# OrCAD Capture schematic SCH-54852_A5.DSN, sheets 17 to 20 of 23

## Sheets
17 C-09 PMIC: size C
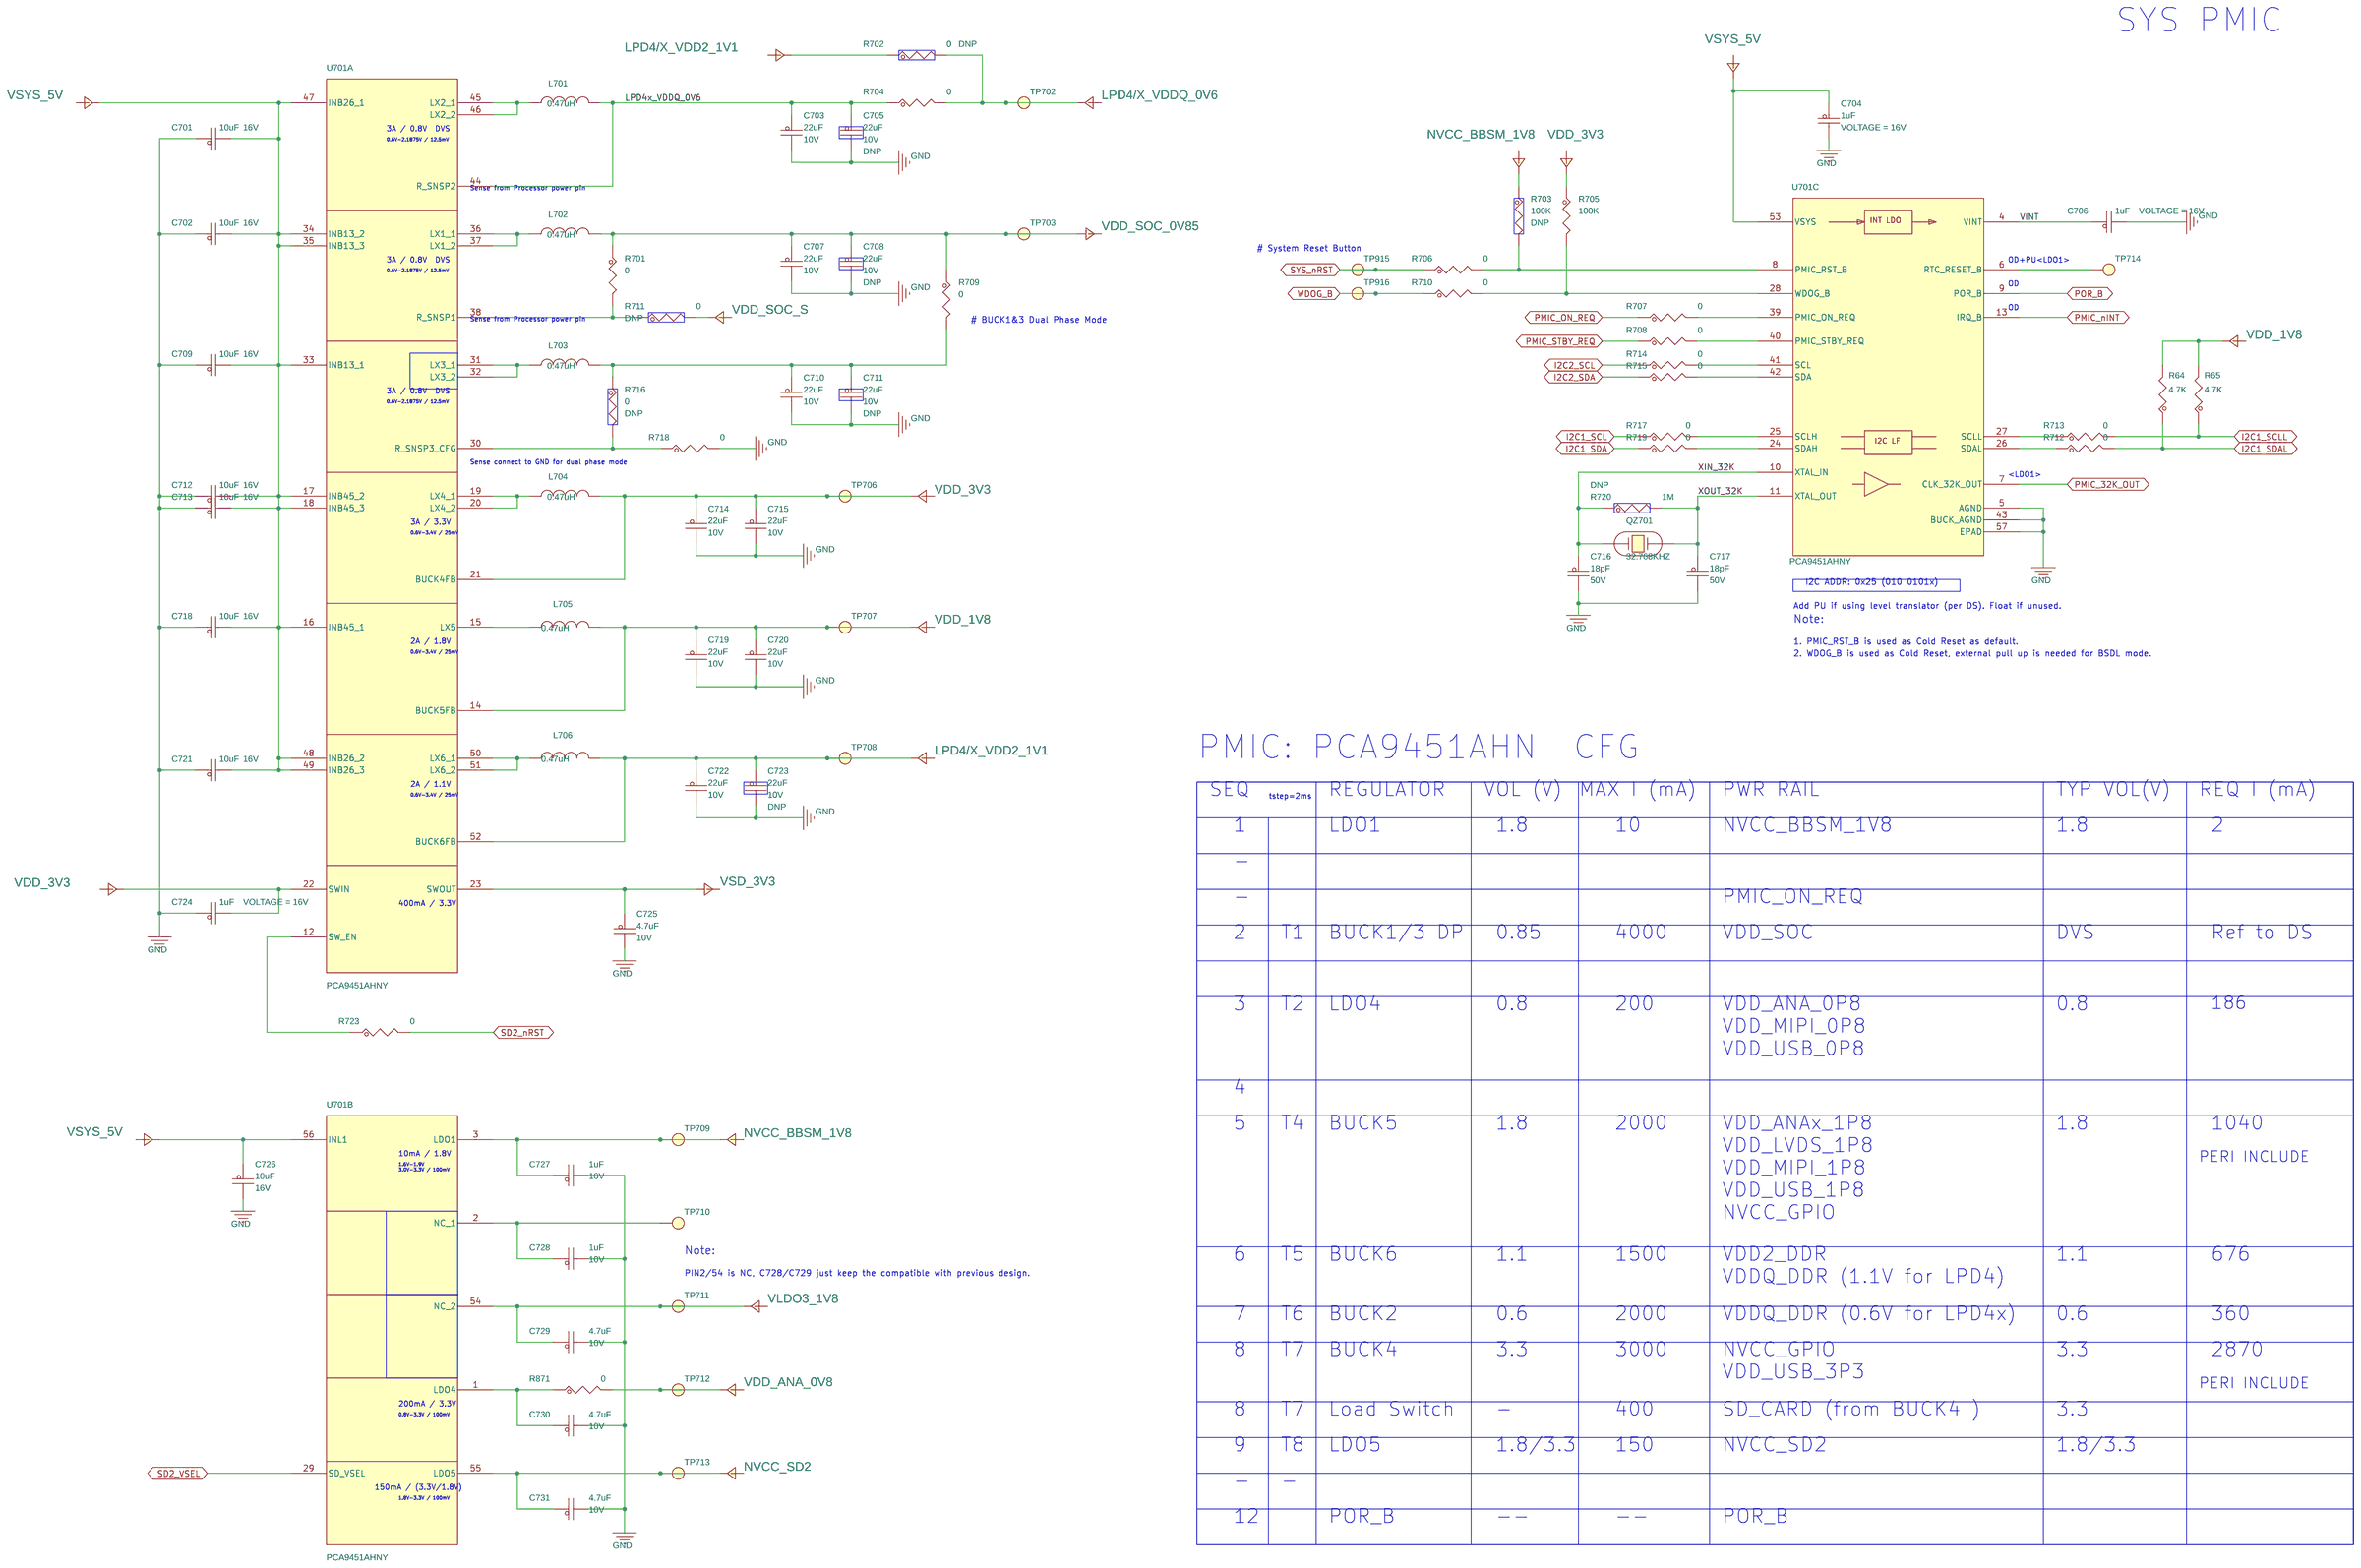
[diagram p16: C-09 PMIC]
18 C-05 LPDDR4/x: size C
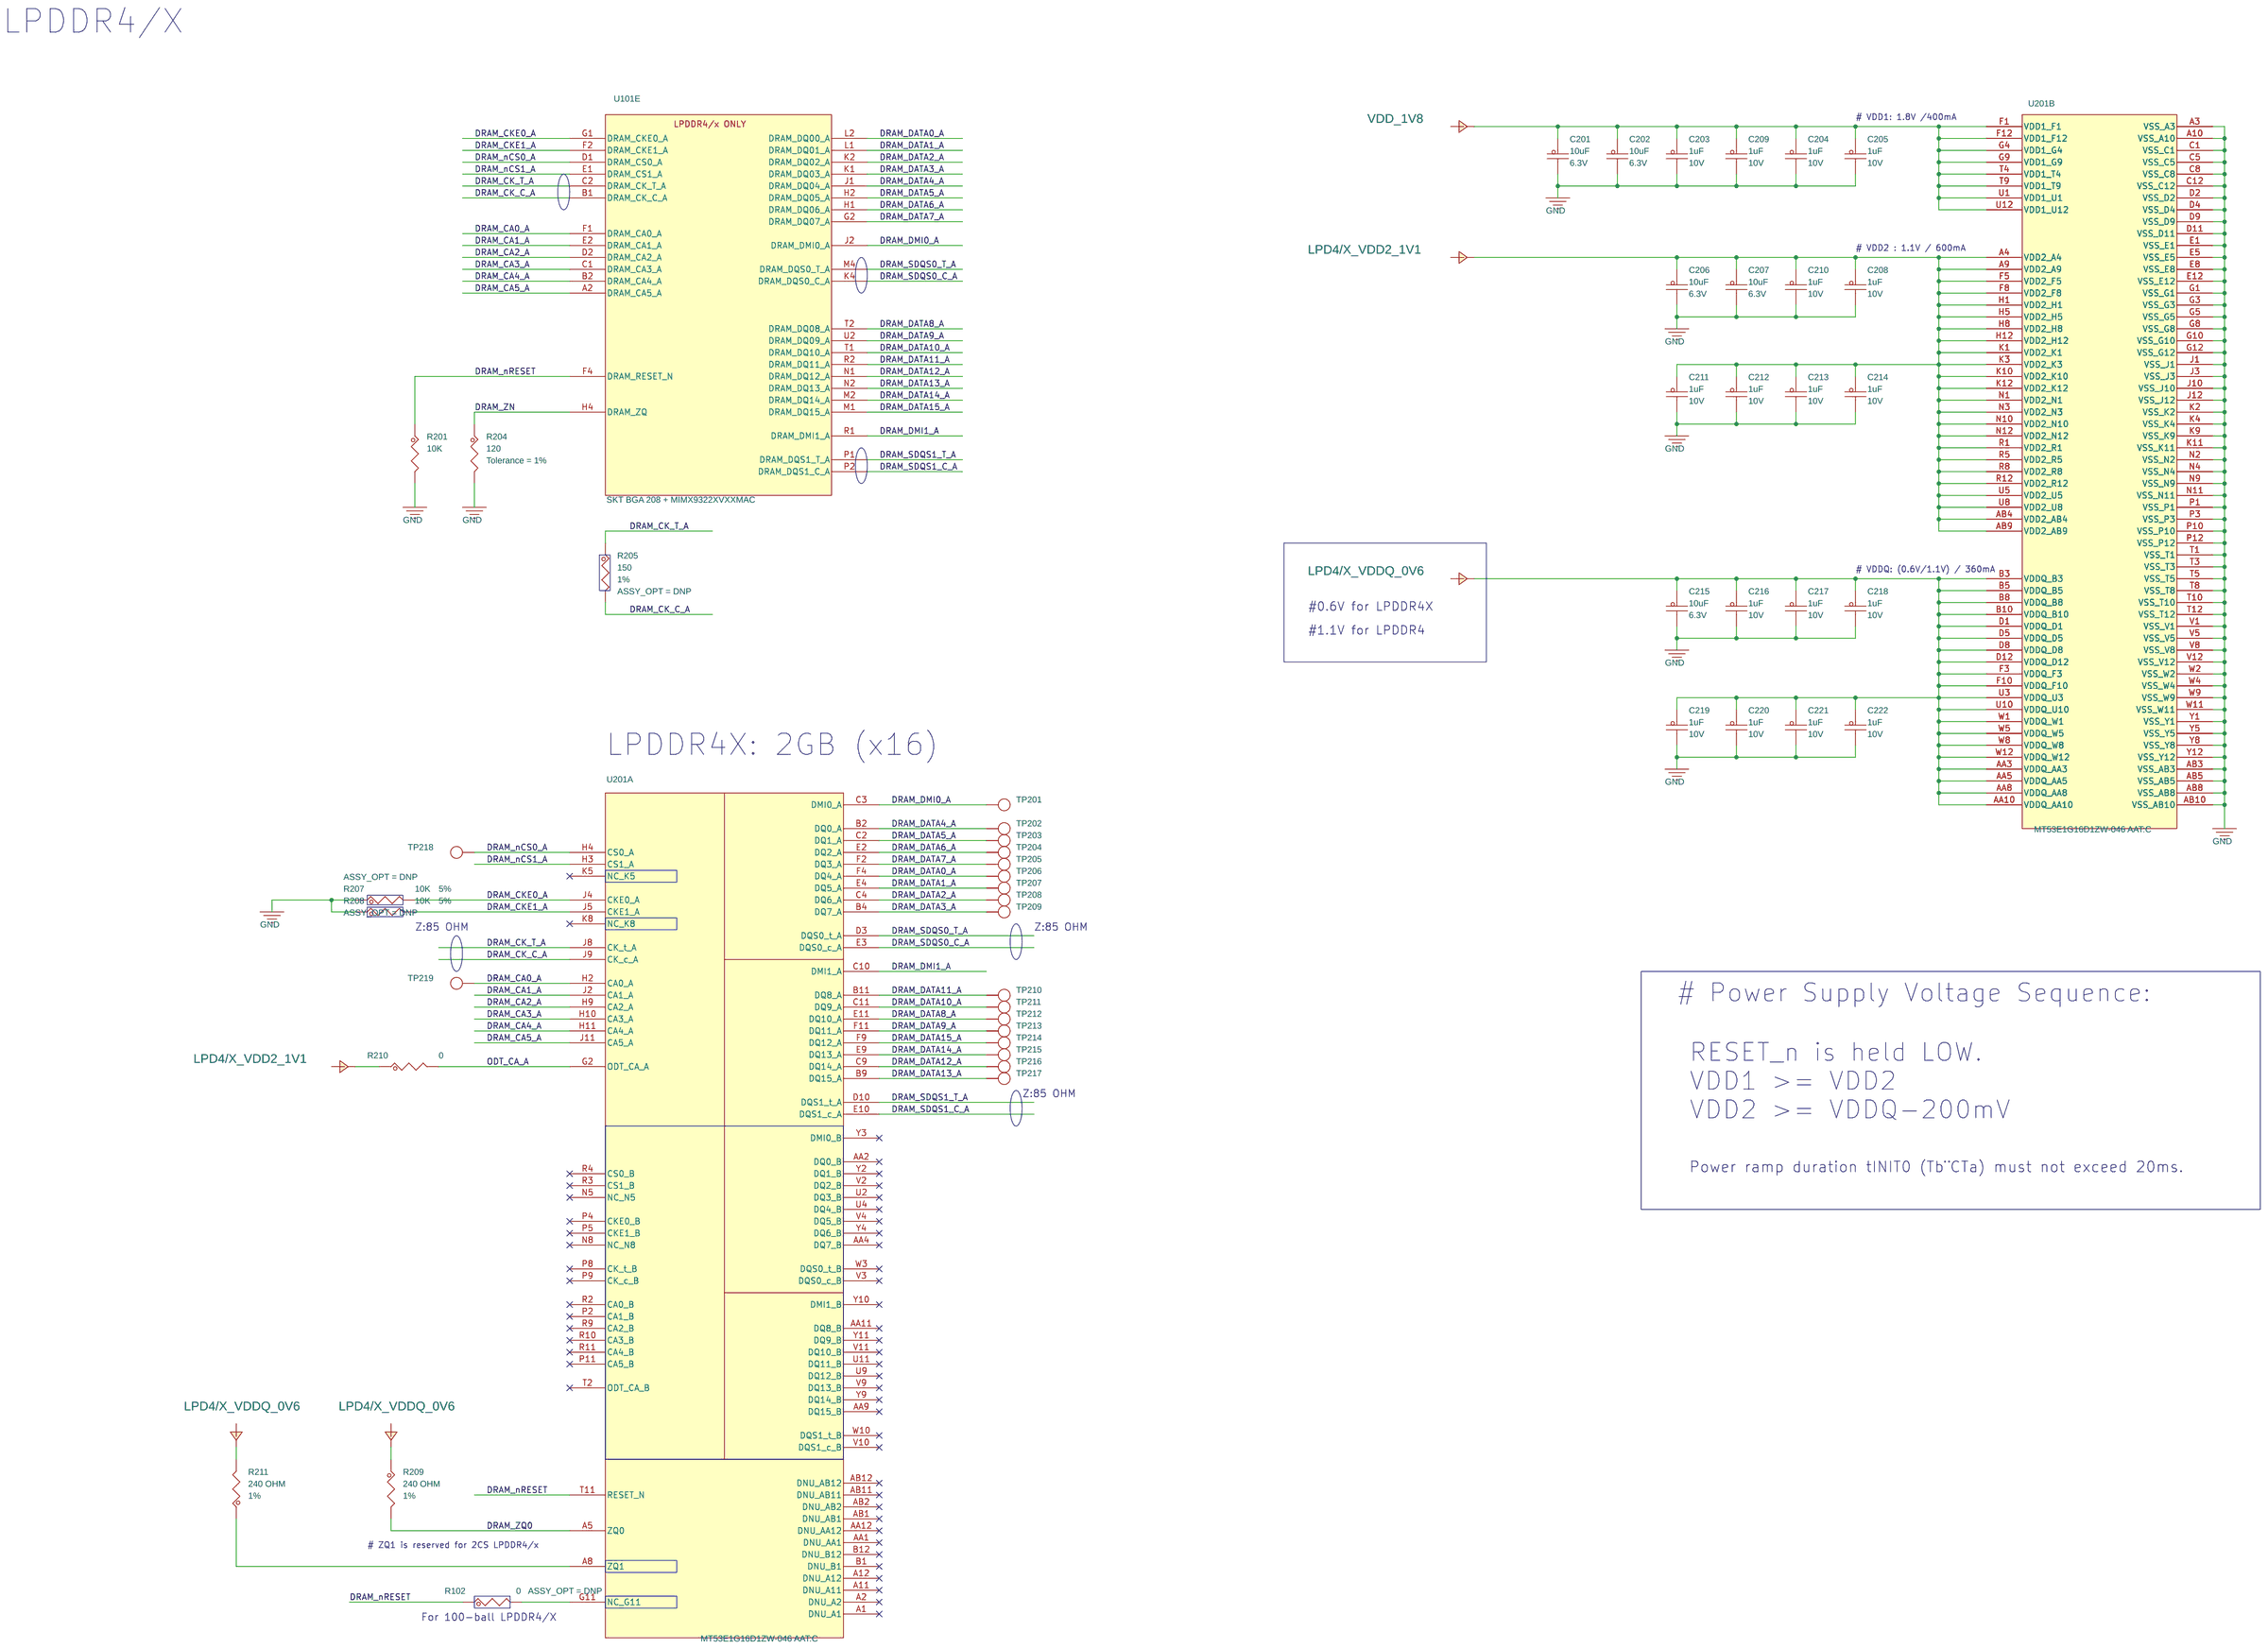
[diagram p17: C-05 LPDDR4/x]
19 C-17 CAN/Ext RTC: size C
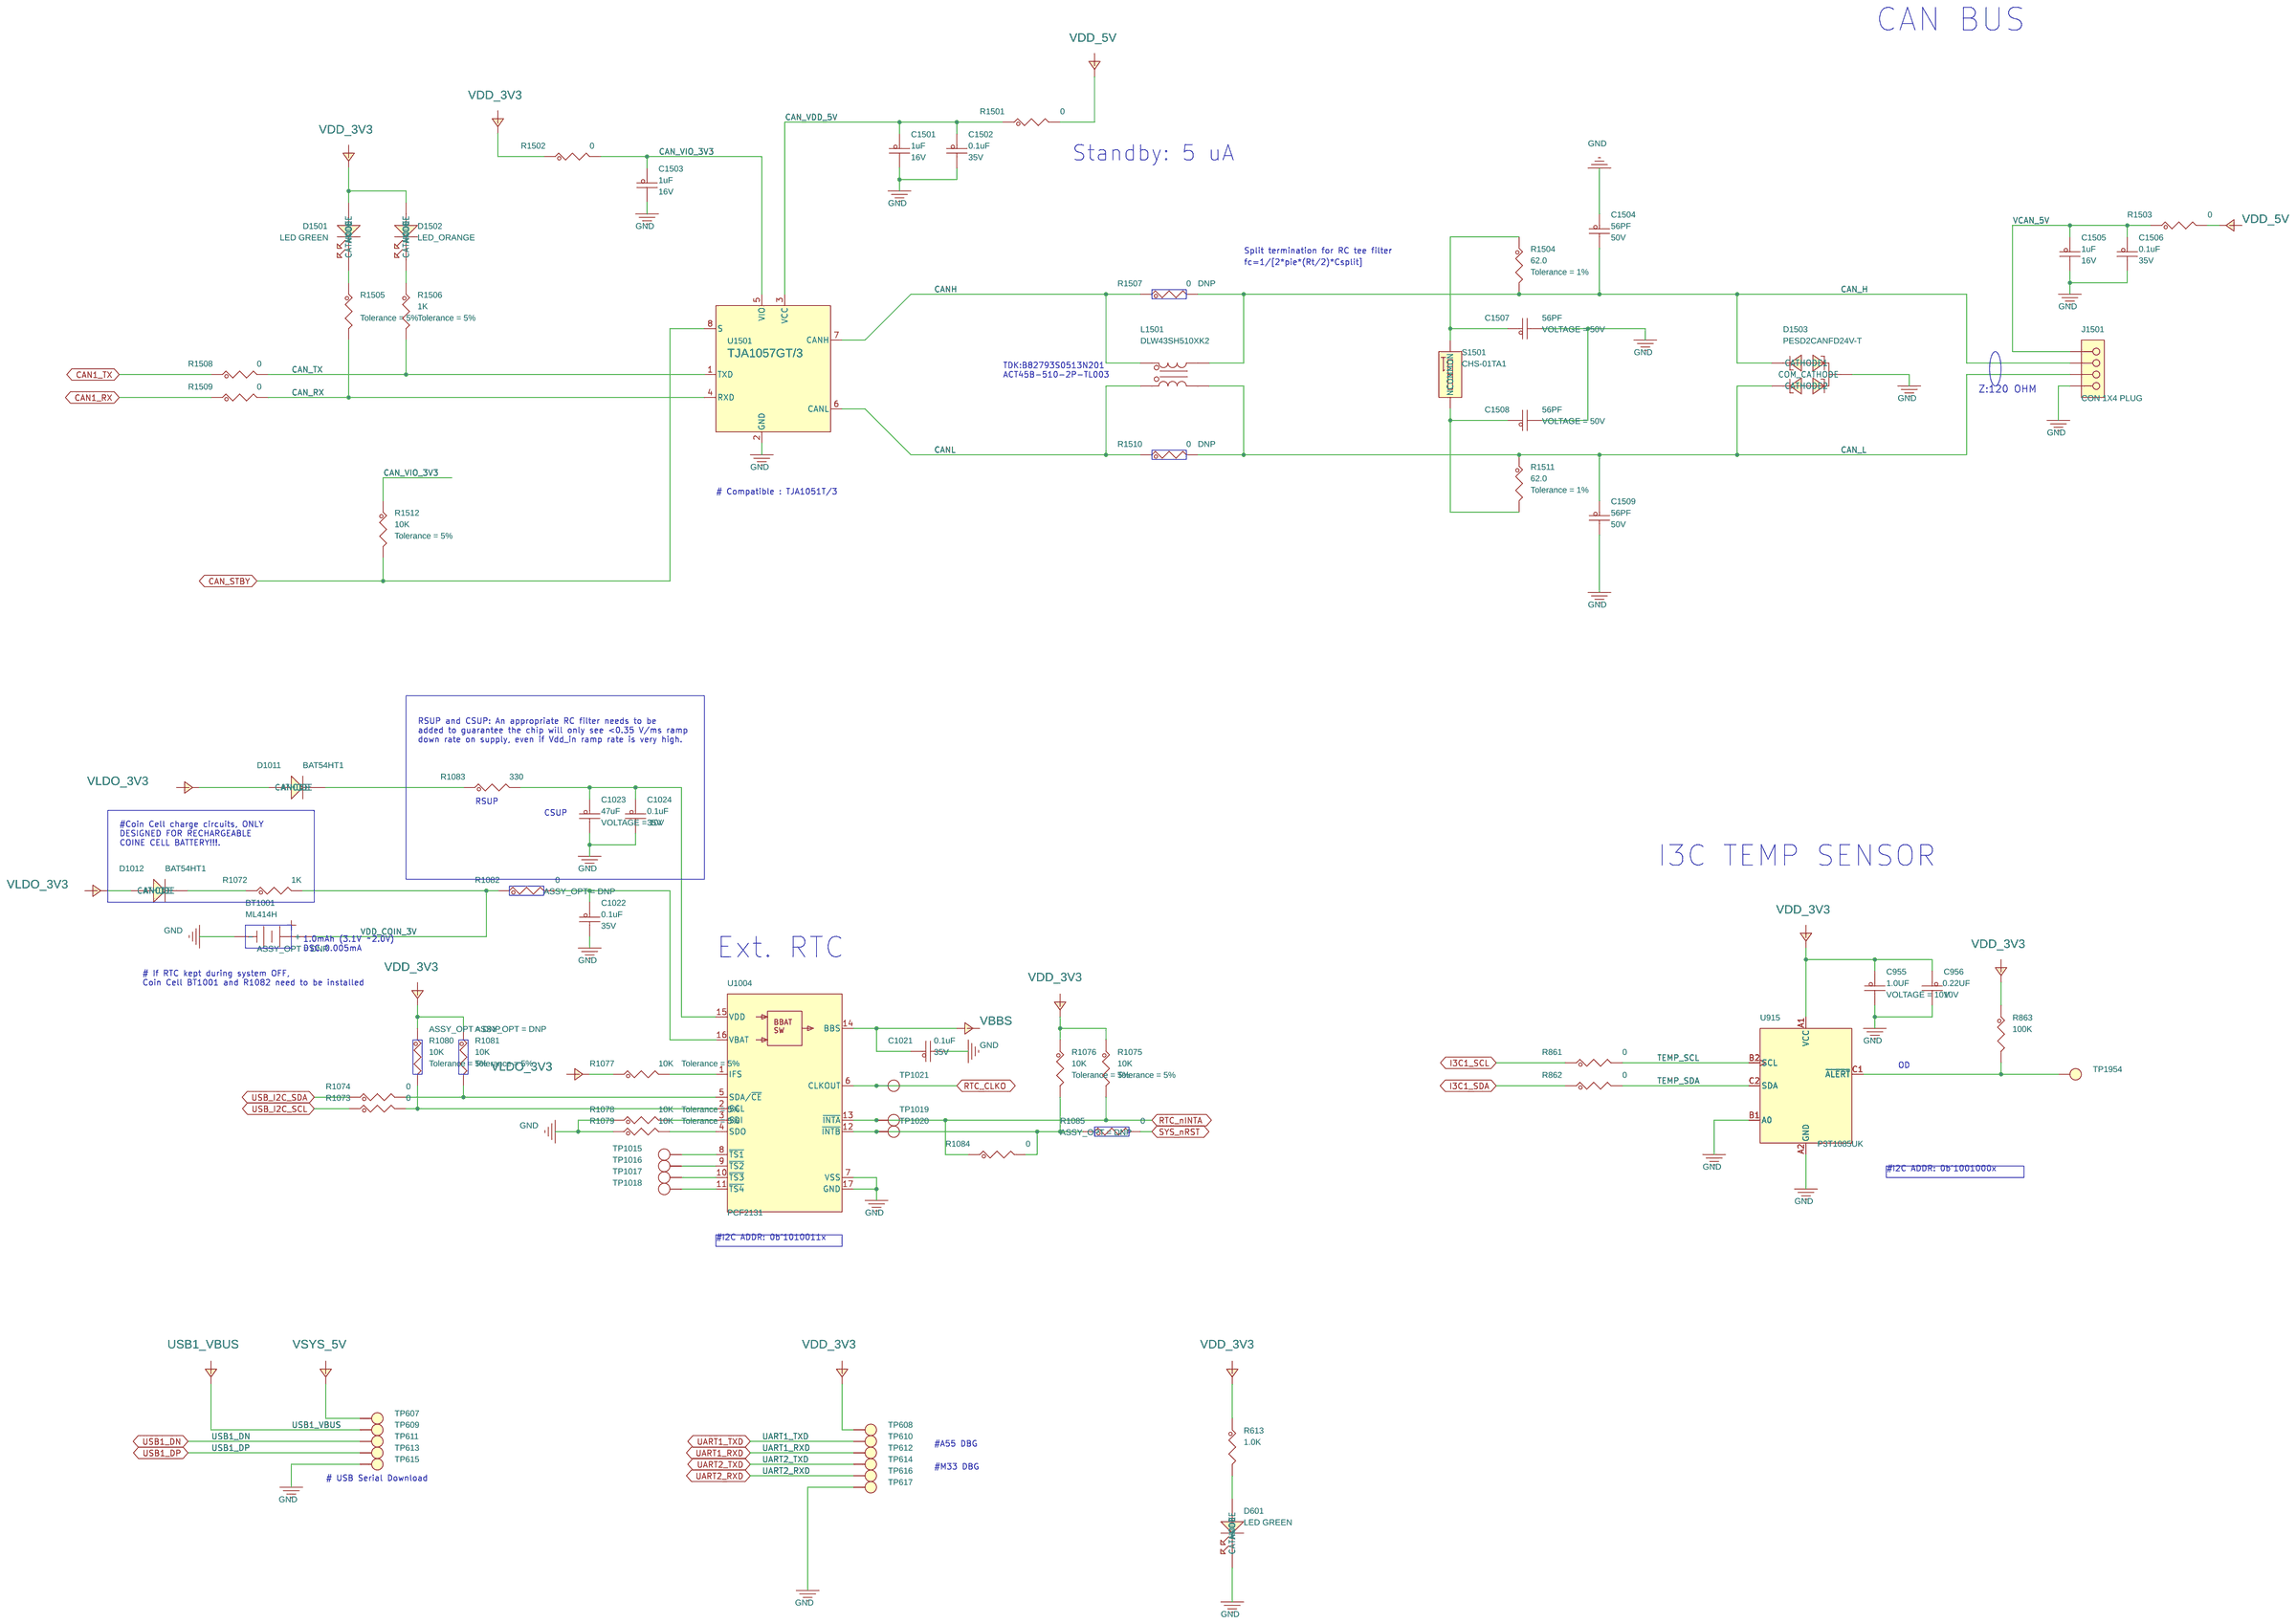
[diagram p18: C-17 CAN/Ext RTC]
20 C-06 CPU IO/PHY: size C
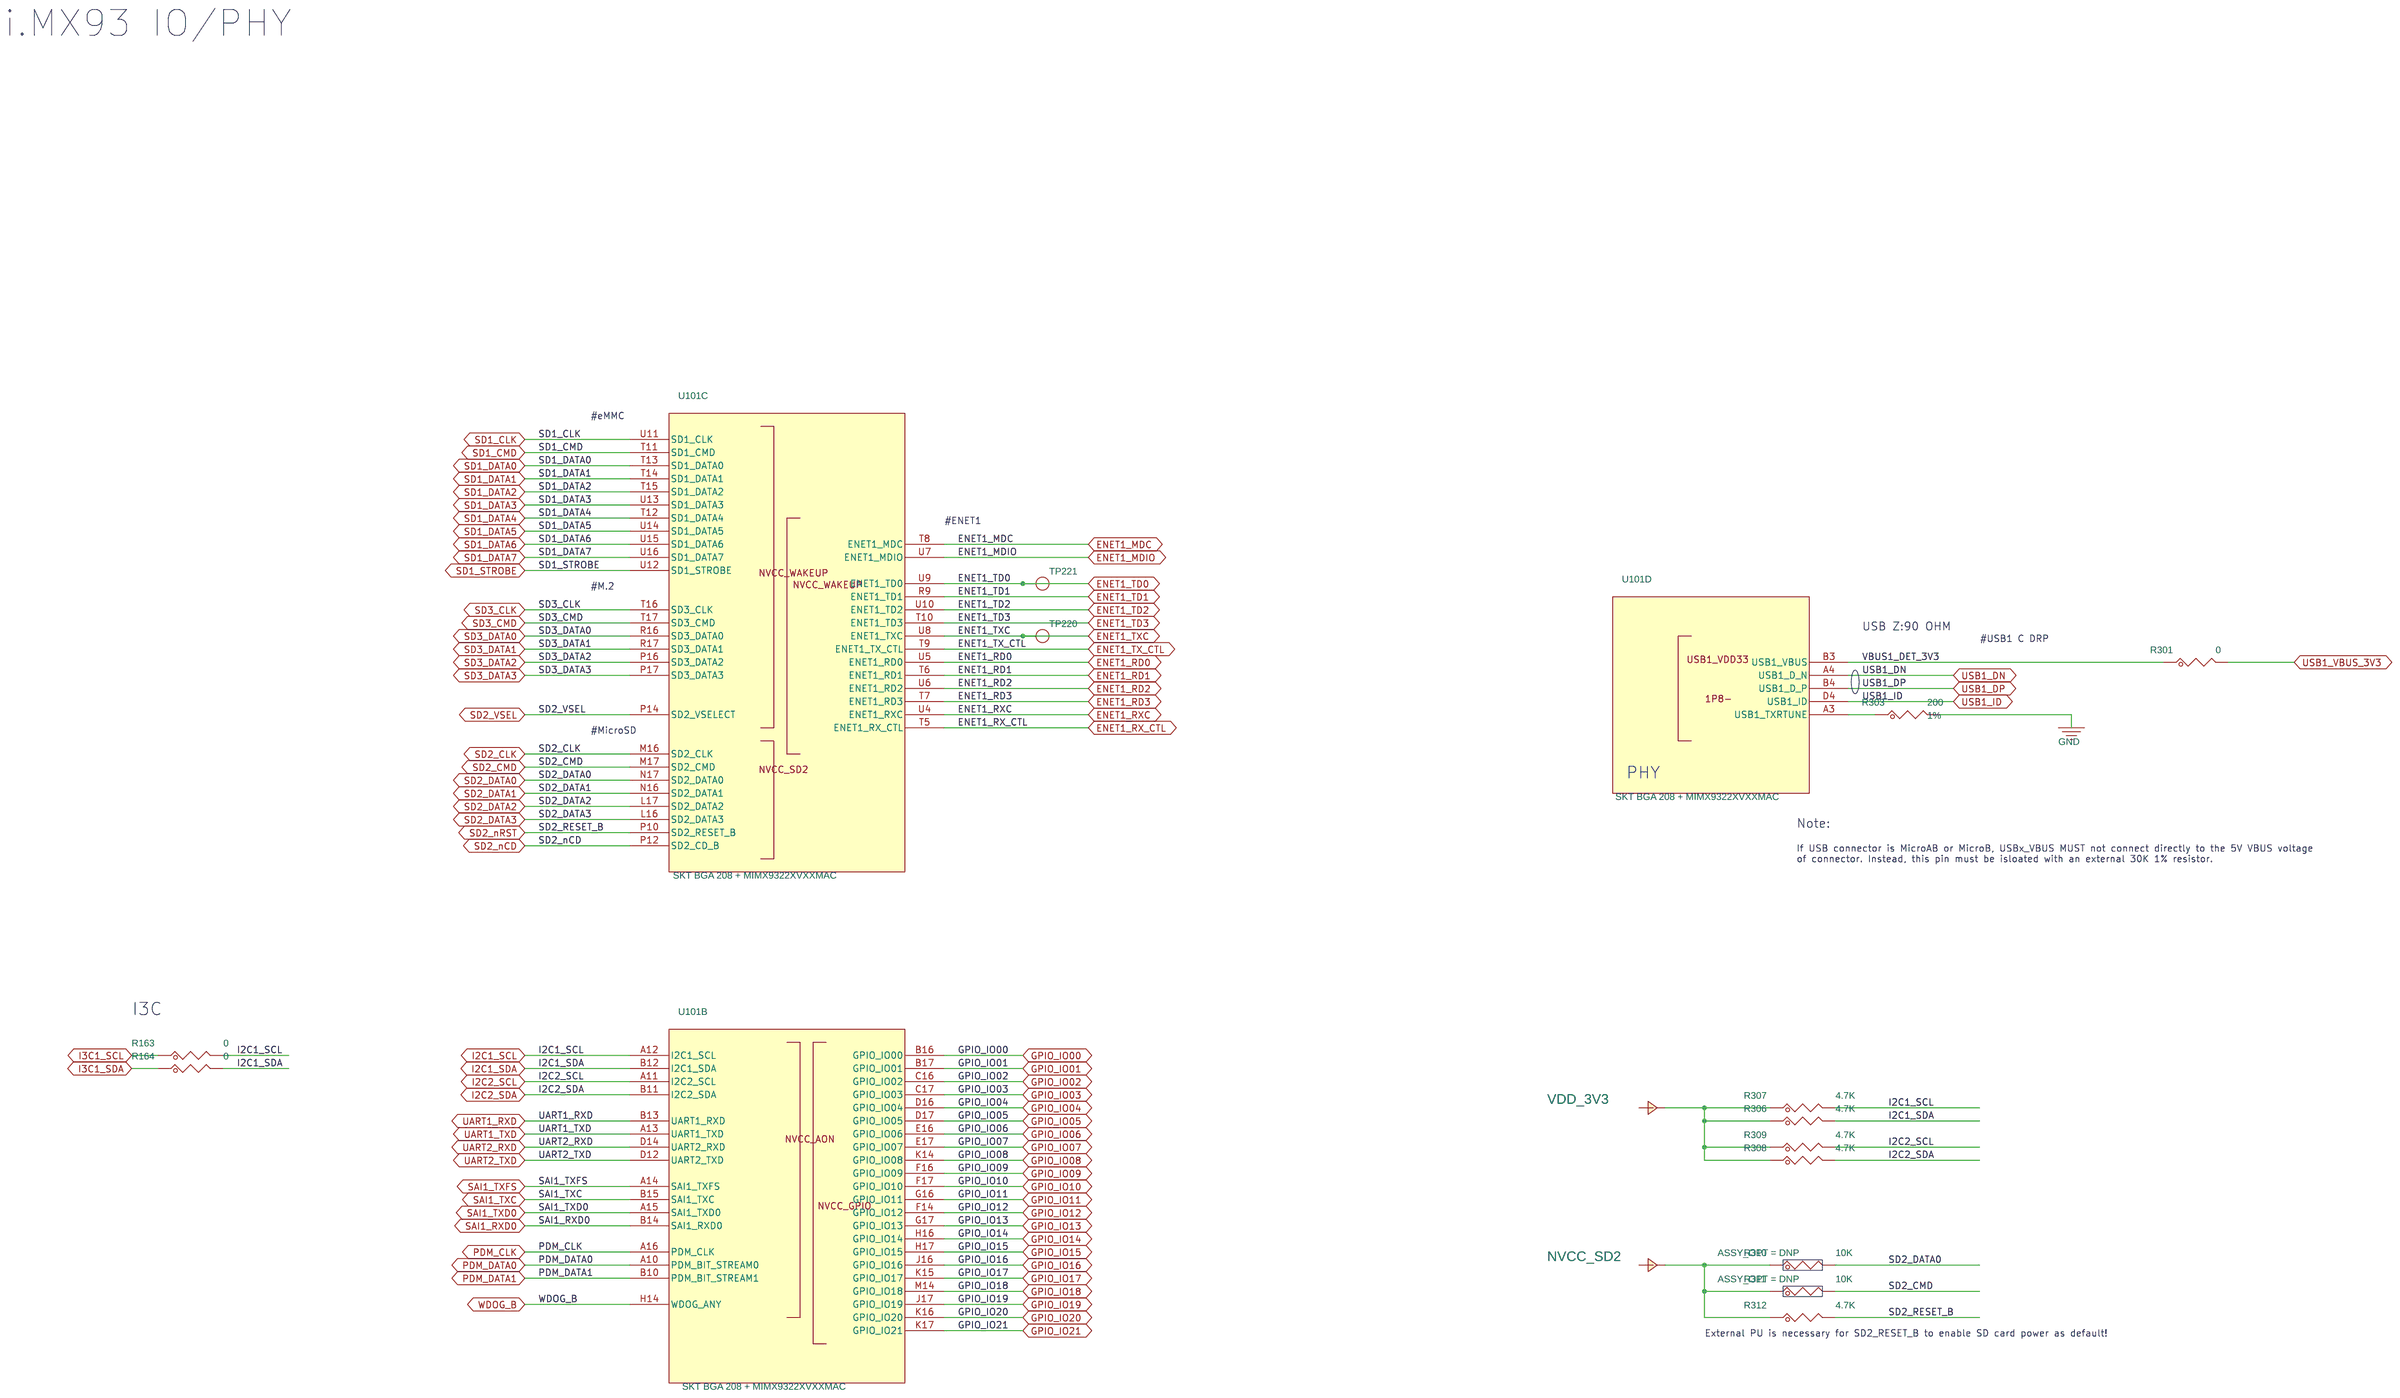
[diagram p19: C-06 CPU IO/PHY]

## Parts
sheet C-05 LPDDR4/x
C201  10uF  [0402_CC]
C202  10uF  [0402_CC]
C203  1uF  [0201_CC]
C204  1uF  [0201_CC]
C205  1uF  [0201_CC]
C206  10uF  [0402_CC]
C207  10uF  [0402_CC]
C208  1uF  [0201_CC]
C209  1uF  [0201_CC]
C210  1uF  [0201_CC]
C211  1uF  [0201_CC]
C212  1uF  [0201_CC]
C213  1uF  [0201_CC]
C214  1uF  [0201_CC]
C215  10uF  [0402_CC]
C216  1uF  [0201_CC]
C217  1uF  [0201_CC]
C218  1uF  [0201_CC]
C219  1uF  [0201_CC]
C220  1uF  [0201_CC]
C221  1uF  [0201_CC]
C222  1uF  [0201_CC]
R102  0  [rc0402_25]
R201  10K  [0402_CC]
R204  120  [0402_CC]
R205  150  [0402_CC]
R207  10K  [0402_CC]
R208  10K  [0402_CC]
R209  240 OHM  [0201_CC]
R210  0  [0402_CC]
R211  240 OHM  [0201_CC]
TP201  TPAD_015  [TPAD_015]
TP202  TPAD_015  [TPAD_015]
TP203  TPAD_015  [TPAD_015]
TP204  TPAD_015  [TPAD_015]
TP205  TPAD_015  [TPAD_015]
TP206  TPAD_015  [TPAD_015]
TP207  TPAD_015  [TPAD_015]
TP208  TPAD_015  [TPAD_015]
TP209  TPAD_015  [TPAD_015]
TP210  TPAD_015  [TPAD_015]
TP211  TPAD_015  [TPAD_015]
TP212  TPAD_015  [TPAD_015]
TP213  TPAD_015  [TPAD_015]
TP214  TPAD_015  [TPAD_015]
TP215  TPAD_015  [TPAD_015]
TP216  TPAD_015  [TPAD_015]
TP217  TPAD_015  [TPAD_015]
TP218  TPAD_015  [TPAD_015]
TP219  TPAD_015  [TPAD_015]
U201  MT53E1G16D1ZW-046 AAT:C  [bga200_0p65x0p8_10x14p5]  (sections A,B)
sheet C-06 CPU IO/PHY
R163  0  [0402_CC]
R164  0  [0402_CC]
R301  0  [0201_CC]
R303  200  [0201_CC]
R306  4.7K  [0402_CC]
R307  4.7K  [0402_CC]
R308  4.7K  [0402_CC]
R309  4.7K  [0402_CC]
R310  10K  [0402_CC]
R311  10K  [0402_CC]
R312  4.7K  [0402_CC]
TP220  TPAD_015  [TPAD_015]
TP221  TPAD_015  [TPAD_015]
U101  SKT BGA 208 + MIMX9322XVXXMAC  [skt_bga208_0p5_17p725sq_elast]  (sections A,B,C,D,E,F)
sheet C-09 PMIC
C701  10uF  [CC0603]
C702  10uF  [CC0603]
C703  22uF  [CC0603]
C704  1uF  [0402_CC]
C705  22uF  [CC0603]
C706  1uF  [0402_CC]
C707  22uF  [CC0603]
C708  22uF  [CC0603]
C709  10uF  [CC0603]
C710  22uF  [CC0603]
C711  22uF  [CC0603]
C712  10uF  [CC0603]
C713  10uF  [CC0603]
C714  22uF  [CC0603]
C715  22uF  [CC0603]
C716  18pF  [0201_CC]
C717  18pF  [0201_CC]
C718  10uF  [CC0603]
C719  22uF  [CC0603]
C720  22uF  [CC0603]
C721  10uF  [CC0603]
C722  22uF  [CC0603]
C723  22uF  [CC0603]
C724  1uF  [0402_CC]
C725  4.7uF  [cc0402_tol0p15]
C726  10uF  [CC0603]
C727  1uF  [0201_CC]
C728  1uF  [0201_CC]
C729  4.7uF  [cc0402_tol0p15]
C730  4.7uF  [cc0402_tol0p15]
C731  4.7uF  [cc0402_tol0p15]
L701  0.47uH  [ind_sph2520]
L702  0.47uH  [ind_sph2520]
L703  0.47uH  [ind_sph2520]
L704  0.47uH  [ind_sph2520]
L705  0.47uH  [IND_2016A]
L706  0.47uH  [IND_2016A]
QZ701  32.768KHZ  [XTAL2-3P2X1P5-SM]
R64  4.7K  [RC0402_25]
R65  4.7K  [RC0402_25]
R701  0  [0402_CC]
R702  0  [0603_CC]
R703  100K  [0402_CC]
R704  0  [0603_CC]
R705  100K  [0402_CC]
R706  0  [0402_CC]
R707  0  [0402_CC]
R708  0  [0402_CC]
R709  0  [0603_CC]
R710  0  [0402_CC]
R711  0  [0402_CC]
R712  0  [0201_CC]
R713  0  [0201_CC]
R714  0  [0402_CC]
R715  0  [0402_CC]
R716  0  [0402_CC]
R717  0  [0201_CC]
R718  0  [0402_CC]
R719  0  [0201_CC]
R720  1M  [0201_CC]
R723  0  [0402_CC]
R871  0  [0402_CC]
TP702  TP_35MIL  [testpoint_35mil]
TP703  TP_35MIL  [testpoint_35mil]
TP706  TP_35MIL  [testpoint_35mil]
TP707  TP_35MIL  [testpoint_35mil]
TP708  TP_35MIL  [testpoint_35mil]
TP709  TP_35MIL  [testpoint_35mil]
TP710  TP_35MIL  [testpoint_35mil]
TP711  TP_35MIL  [testpoint_35mil]
TP712  TP_35MIL  [testpoint_35mil]
TP713  TP_35MIL  [testpoint_35mil]
TP714  TP_35MIL  [testpoint_35mil]
TP915  TP_35MIL  [testpoint_35mil]
TP916  TP_35MIL  [testpoint_35mil]
U701  PCA9451AHNY  [hvqfn56_0p4_7x7_ep4p7mm]  (sections A,B,C)
sheet C-17 CAN/Ext RTC
BT1001  ML414H  [battery_4p8sq_s]
C955  1.0UF  [0402_CC]
C956  0.22UF  [0201_CC]
C1021  0.1uF  [CC0402_25]
C1022  0.1uF  [CC0402_25]
C1023  47uF  [0805_CC]
C1024  0.1uF  [CC0402_25]
C1501  1uF  [CC0402_25]
C1502  0.1uF  [CC0402_25]
C1503  1uF  [CC0402_25]
C1504  56PF  [0402_CC]
C1505  1uF  [CC0402_25]
C1506  0.1uF  [CC0402_25]
C1507  56PF  [0402_CC]
C1508  56PF  [0402_CC]
C1509  56PF  [0402_CC]
D601  LED GREEN  [LED_0603]
D1011  BAT54HT1  [SOD323]
D1012  BAT54HT1  [SOD323]
D1501  LED GREEN  [LED_0603]
D1502  LED_ORANGE  [led_0603_11mil]
D1503  PESD2CANFD24V-T  [sot23_a]
J1501  CON 1X4 PLUG  [con1x4_2mm_th_303h]
L1501  DLW43SH510XK2  [IND_DLW43]
R613  1.0K  [0402_CC]
R861  0  [0402_CC]
R862  0  [0402_CC]
R863  100K  [0402_CC]
R1072  1K  [0402_CC]
R1073  0  [0402_CC]
R1074  0  [0402_CC]
R1075  10K  [0402_CC]
R1076  10K  [0402_CC]
R1077  10K  [0402_CC]
R1078  10K  [0402_CC]
R1079  10K  [0402_CC]
R1080  10K  [0402_CC]
R1081  10K  [0402_CC]
R1082  0  [0402_CC]
R1083  330  [RC0402_25]
R1084  0  [0402_CC]
R1085  0  [0402_CC]
R1501  0  [0402_CC]
R1502  0  [0402_CC]
R1503  0  [0603_CC]
R1504  62.0  [0603_CC]
R1505  2.2K  [0402_CC]
R1506  1K  [0402_CC]
R1507  0  [0402_CC]
R1508  0  [0402_CC]
R1509  0  [0402_CC]
R1510  0  [0402_CC]
R1511  62.0  [0603_CC]
R1512  10K  [0402_CC]
S1501  CHS-01TA1  [sw_2p8x5p7_sm]
TP607  TP_35MIL  [testpoint_35mil]
TP608  TP_35MIL  [testpoint_35mil]
TP609  TP_35MIL  [testpoint_35mil]
TP610  TP_35MIL  [testpoint_35mil]
TP611  TP_35MIL  [testpoint_35mil]
TP612  TP_35MIL  [testpoint_35mil]
TP613  TP_35MIL  [testpoint_35mil]
TP614  TP_35MIL  [testpoint_35mil]
TP615  TP_35MIL  [testpoint_35mil]
TP616  TP_35MIL  [testpoint_35mil]
TP617  TP_35MIL  [testpoint_35mil]
TP1015  TPAD_020  [tpad_020]
TP1016  TPAD_020  [tpad_020]
TP1017  TPAD_020  [tpad_020]
TP1018  TPAD_020  [tpad_020]
TP1019  TPAD_020  [tpad_020]
TP1020  TPAD_020  [tpad_020]
TP1021  TPAD_020  [tpad_020]
TP1954  TP_35MIL  [testpoint_35mil]
U915  P3T1085UK  [wlcsp6_0p4_0p84x1p18]
U1004  PCF2131  [so16_0p5_3p5x4p5_mm]
U1501  TJA1057GT/3  [SO8_1P27_4X5]

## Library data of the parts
C201 C202 C206 C207 C215 = CAP_NP: CAP CER 10UF 6.3V 20% X5R 0402; 3D_Mechanical_Footprint_File: cc0402_tol0p2; AGILE_PN: 150-79163; CAD_APPROVED: Yes; FPLIST: CC0402_25,CC0402_HD,0402_CC; HEIGHT: 0.7 MM; MFG_NAME01: SAMSUNG ELECTRO MECHANICS; MFG_PN01: CL05A106MQ5NUNC; ROHS: Yes; Tolerance: 20%; VOLTAGE: 6.3V
C203-C205 C208-C214 C216-C222 C727 C728 = CAP_NP: CAP CER 1.0uF 10V 10% X5R 0201; AGILE_PN: 150-81088; CAD_APPROVED: Yes; FPLIST: CC0201,CC0201_HD,0201_CC,cc_0201_cir; HEIGHT: 0.35MM; MFG_NAME01: SAMSUNG ELECTRO MECHANICS; MFG_PN01: CL03A105KP3NSNC; Package Size: 0201 (0603 Metric); Package Type: SMD/SMT; ROHS: Yes; Temp Range: -55°C to 85°C; Tolerance: 10%; VOLTAGE: 10V
R102 = RES: RES MF ZERO OHM 1/8W -- AEC-Q200 0402; AGILE_PN: 470-82894; ASSY_OPT: DNP; CAD_APPROVED: Yes; FPLIST: rc0402_25,rc0402_hd,0402_cc; HEIGHT: 0.4 MM; MFG_NAME01: VISHAY; MFG_PN01: RCC04020000Z0ED; Package Size: 0402 [1005 Metric]; Package Type: SMD/SMT; ROHS: Yes; Temp Range: -55 °C to +155 °C
R201 R1075-R1079 R1512 = RES: RES MF 10K 1/16W 5% 0402; AGILE_PN: 470-75557; CAD_APPROVED: Yes; FPLIST: RC0402_25,RC0402_HD,0402_CC; HEIGHT: 0.4 MM; MFG_NAME01: VISHAY INTERTECHNOLOGY; MFG_PN01: CRCW040210K0JNED; ROHS: Yes; Tolerance: 5%
R204 = RES: RES MF 120 OHM 1/10W 1% AEC-Q200 0402; AGILE_PN: 470-82646; CAD_APPROVED: Yes; FPLIST: RC0402_25,RC0402_HD,0402_CC; HEIGHT: 0.4MM; MFG_NAME01: Panasonic; MFG_PN01: ERJ-2RKF1200X; ROHS: Yes; Temp Range: -55°C ~ 155°C; Tolerance: 1%; VOLTAGE: 1/10W
R205 = RES: RES MF 150 OHM 1/16W 1% 0402; AGILE_PN: 470-75353; ASSY_OPT: DNP; CAD_APPROVED: Yes; FPLIST: RC0402_25,RC0402_HD,0402_CC; HEIGHT: 0.4MM; MFG_NAME01: NIC COMPONENTS CORP; MFG_PN01: NRCL04F1500TRF; ROHS: Yes; Tolerance: 1%
R207 R208 R310 R311 R1080 R1081 = RES: RES MF 10K 1/16W 5% 0402; AGILE_PN: 470-75557; ASSY_OPT: DNP; CAD_APPROVED: Yes; FPLIST: RC0402_25,RC0402_HD,0402_CC; HEIGHT: 0.4 MM; MFG_NAME01: VISHAY INTERTECHNOLOGY; MFG_PN01: CRCW040210K0JNED; ROHS: Yes; Tolerance: 5%
R209 R211 = RES: RES MF 240 OHM 1/20W 1% 0201; AGILE_PN: 470-81317; CAD_APPROVED: Yes; FPLIST: CC0201,CC0201_HD,0201_CC; HEIGHT: 0.26MM; MFG_NAME01: YAGEO AMERICA; MFG_PN01: RC0201FR-07240RL; ROHS: Yes; Temp Range: -55°C ~ 125°C; Temp_Range: -55°C ~ 125°C; Tolerance: 1%; VOLTAGE: 25V
R163 R164 R210 R701 R706-R708 R710 R714 R715 R718 R723 R861 R862 R1073 R1074 R1084 R1501 R1502 = RES: RES MF ZERO OHM 1/16W 5% 0402; AGILE_PN: 470-75394; CAD_APPROVED: Yes; FPLIST: RC0402_25,RC0402_HD,RC0402_X2,0402_CC; HEIGHT: 0.45 MM; MFG_NAME01: YAGEO AMERICA; MFG_PN01: RC0402JR-070RL; ROHS: Yes; Tolerance: 5%; VOLTAGE: 1/16W
TP201-TP221 = TestLoop: TEST POINT PAD 15MIL DIA SMT, NO PART TO ORDER; AGILE_PN: 211-76645; CAD_APPROVED: Yes; HEIGHT: 0.1MM; MFG_NAME01: NOTACOMPONENT; MFG_PN01: NOTACOMPONENT; ROHS: Yes
U201 = MT53E1G16D1FW-046_200P_A: IC MEM LPDDR4/LPDDR4X SDRAM 1GX16 1.1V AEC-Q100 TFBGA200; 3D_Mechanical_Footprint_File: http://fcl.am.freescale.net/ALLEGRO/step/bga200_0p65x0p8_10x14p5.STEP; AGILE_PN: 334-10016; CAD_APPROVED: Yes; HEIGHT: 1.1; MFG_NAME01: Micron; Package Size: 10.0 x 14.5 x 1.0MM; ROHS: NULL; Supply Voltage: 1.1V; Temp Range: -40C to +105C; VOLTAGE: 1.1V
R301 R712 R713 R717 R719 = RES: RES MF ZERO OHM 1/20W -- 0201; AGILE_PN: 470-76631; CAD_APPROVED: Yes; FPLIST: RC0201,0201_CC,RC0201_X2; HEIGHT: 0.30 MM; MFG_NAME01: BOURNS; MFG_PN01: CR0201-J/-000GLF; ROHS: Yes
R303 = RES: RES MF 200 OHM 1/20W 1% 0201; AGILE_PN: 470-82323; CAD_APPROVED: Yes; FPLIST: RC0201,0201_CC; HEIGHT: 0.26MM; MFG_NAME01: YAGEO AMERICA; MFG_PN01: RC0201FR-07200RL; ROHS: Yes; Temp Range: -55°C ~ 125°C; Temp_Range: -55°C ~ 125°C; Tolerance: 1%; VOLTAGE: 25V
R64 R65 R306-R309 R312 = RES: RES MF 4.7K 1/10W 5% AEC-Q200 0402; AGILE_PN: 470-82064; CAD_APPROVED: Yes; FPLIST: RC0402_25,RC0402_HD,0402_CC,RC0402_X2; HEIGHT: 0.41mm; MFG_NAME01: KOA SPEER; MFG_PN01: RK73B1ETTP472J; ROHS: Yes; Temp Range: -55C to +155C; Temp_Range: -55C to +155C; Tolerance: 5%; VOLTAGE: 50V
U101 = MIMX9322XVXxMAB_BGA208: SUBASSEMBLY SKT 208 BGA ELASTOMER SMT 0.5MM 414H AU + IC CPU CORTEX 2xA55 1.7GHz 3.2GT/s DDR -- FCPBGA208; AGILE_PN: TMP-CIP-20687; CAD_APPROVED: Yes; HEIGHT: 10.503mm; MFG_NAME01: SUBASSEMBLY; MFG_PN01: 211-81858,330-10033; PRE_APN: 750-10191; Package Type: SMD/SMT; ROHS: Yes
C701 C702 C709 C712 C713 C718 C721 C726 = CAP_NP: CAP CER 10.0uF 16V 10% X5R 0603; AGILE_PN: 150-80060; CAD_APPROVED: Yes; FPLIST: CC0603_OV,CC0603,0603_CC,cc0603_0805_nsp; HEIGHT: 0.9MM; MFG_NAME01: MURATA; MFG_PN01: GRM188R61C106KAALD; Package Size: 0603; Package Type: SMT; ROHS: Yes; Temp Range: -55°C to +85°C; Temp_Range: -55°C to +85°C; Tolerance: 10%; VOLTAGE: 16V
C703 C707 C710 C714 C715 C719 C720 C722 = CAP_NP: CAP CER 22uF 10V 20% X5R 0603; AGILE_PN: 150-79530; CAD_APPROVED: Yes; FPLIST: CC0603_OV,CC0603,0603_cc_tol; HEIGHT: 1MM; MFG_NAME01: TDK; MFG_PN01: C1608X5R1A226M080AC; Package Size: 0603; ROHS: Yes; SIGNAL_MODEL: DEFAULT_CAPACITOR_2.2e+07pF_2_1; Tolerance: 20%; VOLTAGE: 10V; WVDC: 6.3V
C704 C706 C724 C1501 C1503 C1505 = CAP_NP: CAP CER 1uF 16V 10% X5R 0402; AGILE_PN: 150-78973; CAD_APPROVED: Yes; FPLIST: CC0402_25,CC0402_HD,0402_CC,capc0402_l; HEIGHT: 0.55 MM; MFG_NAME01: YAGEO; MFG_PN01: CC0402KRX5R7BB105; ROHS: Yes; Tolerance: 10%; VOLTAGE: 16V
C705 C708 C711 C723 = CAP_NP: CAP CER 22uF 10V 20% X5R 0603; AGILE_PN: 150-79530; ASSY_OPT: DNP; CAD_APPROVED: Yes; FPLIST: CC0603_OV,CC0603,0603_cc_tol; HEIGHT: 1MM; MFG_NAME01: TDK; MFG_PN01: C1608X5R1A226M080AC; Package Size: 0603; ROHS: Yes; SIGNAL_MODEL: DEFAULT_CAPACITOR_2.2e+07pF_2_1; Tolerance: 20%; VOLTAGE: 10V; WVDC: 6.3V
C716 C717 = CAP_NP: CAP CER 18pF 50V 5% C0G 0201; AGILE_PN: 150-79476; CAD_APPROVED: Yes; FPLIST: CC0201,CC0201_HD,0201_CC; HEIGHT: 0.33MM; MFG_NAME01: MURATA; MFG_PN01: GRM0335C1H180JA01D; Package Size: 0201; Package Type: &#966;180mm Paper taping; ROHS: Yes; Tolerance: 5%; VOLTAGE: 50V
C725 C729-C731 = CAP_NP: CAP CER 4.7uF 10V 10% X5R 0402; AGILE_PN: 150-80044; CAD_APPROVED: Yes; FPLIST: cc0402_tol0p15,cc0402_tol0p15_ov,0402_cc_nsp; HEIGHT: 0.65MM; MFG_NAME01: SAMSUNG ELECTRO MECHANICS; MFG_PN01: CL05A475KP5NRNC; ROHS: Yes; Tolerance: 10%; VOLTAGE: 10V
L701-L704 = INDUCTOR: IND PWR 0.47uH@1MHZ 4.7A 20% SMT; AGILE_PN: 180-78647; CAD_APPROVED: Yes; HEIGHT: 1.2MM; MFG_NAME01: SHENZHEN SUNLORD ELECTRONICS CO., LTD; MFG_PN01: WPN252012ER47MT; PART_TYPE: INDUCTOR\POWER; ROHS: Yes; TOL: 20%; Temp Range: -40°C to +125°C; Temp_Range: -40°C to +125°C; Tolerance: 20%
L705 L706 = INDUCTOR: IND PWR 0.47uH@1MHz 3.4A 20% 2016; AGILE_PN: 180-78995; CAD_APPROVED: Yes; HEIGHT: 1.2MM; MFG_NAME01: SHENZHEN SUNLORD ELECTRONICS CO., LTD; MFG_PN01: WPN201612HR47MT; PART_TYPE: INDUCTOR\POWER; Package Size: 2x1.6x1.2 mm; ROHS: Yes; Temp Range: -40°C to 125°C; Temp_Range: -40°C to 125°C; Tolerance: 20%
QZ701 = XTAL: XTAL 32.768KHZ 12.5PF 20PPM 3.2X1.5MM SMT; AGILE_PN: 230-77653; CAD_APPROVED: Yes; HEIGHT: 0.9MM; MFG_NAME01: Abracon Corporation; MFG_PN01: ABS07-32.768KHZ-T; ROHS: Yes
R702 = RES: RES MF ZERO OHM 1/10W -- 0603; AGILE_PN: 470-80866; ASSY_OPT: DNP; CAD_APPROVED: Yes; FPLIST: RC0603_OV,RC0603,R603-X2,0603_CC,IND_0603HP_NSP,CC0603_OV_NSP; HEIGHT: 0.6MM; MFG_NAME01: YAGEO AMERICA; MFG_PN01: RC0603FR-070RL; ROHS: Yes; Temp Range: –55 °C to +155 °C
R703 = RES: RES MF 100K 1/16W 5% 0402; AGILE_PN: 470-75597; ASSY_OPT: DNP; CAD_APPROVED: Yes; FPLIST: RC0402_25,RC0402_HD,0402_CC; HEIGHT: 0.40 MM; MFG_NAME01: VENKEL COMPANY; MFG_PN01: CR0402-16W-104JT; ROHS: Yes; Temp Range: -55C to +155C; Tolerance: 5%; VOLTAGE: 50V
R704 R709 R1503 = RES: RES MF ZERO OHM 1/10W -- 0603; AGILE_PN: 470-80866; CAD_APPROVED: Yes; FPLIST: RC0603_OV,RC0603,R603-X2,0603_CC,IND_0603HP_NSP,CC0603_OV_NSP; HEIGHT: 0.6MM; MFG_NAME01: YAGEO AMERICA; MFG_PN01: RC0603FR-070RL; ROHS: Yes; Temp Range: –55 °C to +155 °C
R705 R863 = RES: RES MF 100K 1/16W 5% 0402; AGILE_PN: 470-75597; CAD_APPROVED: Yes; FPLIST: RC0402_25,RC0402_HD,0402_CC; HEIGHT: 0.40 MM; MFG_NAME01: VENKEL COMPANY; MFG_PN01: CR0402-16W-104JT; ROHS: Yes; Temp Range: -55C to +155C; Tolerance: 5%; VOLTAGE: 50V
R711 R716 R1082 R1085 = RES: RES MF ZERO OHM 1/16W 5% 0402; AGILE_PN: 470-75394; ASSY_OPT: DNP; CAD_APPROVED: Yes; FPLIST: RC0402_25,RC0402_HD,RC0402_X2,0402_CC; HEIGHT: 0.45 MM; MFG_NAME01: YAGEO AMERICA; MFG_PN01: RC0402JR-070RL; ROHS: Yes; Tolerance: 5%; VOLTAGE: 1/16W
R720 = RES: RES MF 1.0M 1/20W 5% AEC-Q200 0201; AGILE_PN: 470-79975; ASSY_OPT: DNP; CAD_APPROVED: Yes; FPLIST: RC0201,0201_CC; HEIGHT: 0.26MM; MFG_NAME01: PANASONIC; MFG_PN01: ERJ-1GNJ105C; ROHS: Yes; Temp Range: 55°C ~ 125°C; Temp_Range: 55°C ~ 125°C; Tolerance: 5%; VOLTAGE: 25V
R871 = RES: RES MF ZERO OHM 1/16W 5% 0402; AGILE_PN: 470-75394; CAD_APPROVED: Yes; FPLIST: RC0402_25,RC0402_HD,RC0402_X2,0402_CC; HEIGHT: 0.45 MM; MFG_NAME01: ROHM; MFG_PN01: MCR01MZPJ000; ROHS: Yes; Tolerance: 5%; VOLTAGE: 1/16W
TP607-TP617 TP702 TP703 TP706-TP714 TP915 TP916 TP1954 = T_POINT_R: TEST POINT PAD .035 SMT, no part to order; AGILE_PN: 510-75618; ASSY_OPT: DNP; CAD_APPROVED: Yes; HEIGHT: 0.1MM; ROHS: Yes
U701 = PCA9451AHNY: IC POWER MANAGEMENT 2.7-5.5V HVQFN56; 3D_Mechanical_Footprint_File: http://fcl.am.freescale.net/ALLEGRO/step/hvqfn56_0p4_7x7_ep4p7mm.step; AGILE_PN: TMP-CIP-8249; CAD_APPROVED: Yes; HEIGHT: 1MM; MFG_NAME01: NXP SEMICONDUCTORS; PRE_APN: 315-83273; Package Size: 7x7; ROHS: Yes
BT1001 = BATTERY: BATTERY LITHIUM -- 3V 1MAH SMD; AGILE_PN: 801-76342; ASSY_OPT: DNP; CAD_APPROVED: Yes; HEIGHT: 1.77mm; MFG_NAME01: SEIKO; MFG_PN01: ML414H  IV01E; ROHS: YES; Temp Range: -20°C to 60°C
C955 = CAP_NP: CAP CER 1.0UF 10V 10% X5R 0402; AGILE_PN: 150-75772; CAD_APPROVED: Yes; FPLIST: CC0402_25,CC0402_HD,0402_CC; HEIGHT: 0.6MM; MFG_NAME01: YAGEO AMERICA; MFG_PN01: CC0402KRX5R6BB105; Package Size: 0402; ROHS: Yes; SIGNAL_MODEL: DEFAULT_CAPACITOR_1e+06pF_2_1; TOL: 10%; VOLTAGE: 10V; voltage rating: 10V
C956 = CAP_NP: CAP CER 0.22UF 10V 20% X5R 0201; AGILE_PN: 150-78815; CAD_APPROVED: Yes; FPLIST: CC0201,CC0201_HD,0201_CC,0201_CC_012SM_NSP; HEIGHT: 0.33MM; MFG_NAME01: Taiyo Yuden; MFG_PN01: LMK063BJ224MP-F; ROHS: Yes; Tolerance: 20%; VOLTAGE: 10V
C1021 = CAP_NP: CAP CER 0.1UF 35V 10% X5R 0402; AGILE_PN: 150-78506; CAD_APPROVED: Yes; EN: 102-1-02300; FPLIST: CC0402_25,CC0402_HD,0402_CC,capc0402_l; HEIGHT: 0.55MM; MFG_NAME01: TAIYO YUDEN; MFG_PN01: GMK105BJ104KV-F; ROHS: Yes; TOL: 10%; Tolerance: 10%; VOLTAGE: 35V
C1022 C1024 C1502 C1506 = CAP_NP: CAP CER 0.1UF 35V 10% X5R 0402; AGILE_PN: 150-78506; CAD_APPROVED: Yes; FPLIST: CC0402_25,CC0402_HD,0402_CC,capc0402_l; HEIGHT: 0.55MM; MFG_NAME01: TAIYO YUDEN; MFG_PN01: GMK105BJ104KV-F; ROHS: Yes; Tolerance: 10%; VOLTAGE: 35V
C1023 = CAP_NP: CAP CER 47uF 10V 20% X5R 0805; AGILE_PN: 150-78979; CAD_APPROVED: Yes; FPLIST: CC0805_OV,CC0805,0805_CC; HEIGHT: 1.45 MM; MFG_NAME01: TDK; MFG_PN01: C2012X5R1A476M125AC; ROHS: Yes; Tolerance: 20%; VOLTAGE: 10V
C1504 C1509 = CAP_NP: CAP CER 56PF 50V 5% C0G 0402; AGILE_PN: 150-30269; CAD_APPROVED: Yes; FPLIST: CC0402_25,CC0402_HD,0402_CC; HEIGHT: 0.55 MM; MFG_NAME01: VENKEL COMPANY; MFG_PN01: C0402C0G500-560JNE; ROHS: Yes; Tolerance: 5%; VOLTAGE: 50V
C1507 C1508 = CAP_NP: CAP CER 56PF 50V 5% C0G 0402; AGILE_PN: 150-30269; CAD_APPROVED: Yes; FPLIST: CC0402_25,CC0402_HD,0402_CC,capc0402_l; HEIGHT: 0.55 MM; MFG_NAME01: VENKEL COMPANY; MFG_PN01: C0402C0G500-560JNE; ROHS: Yes; Tolerance: 5%; VOLTAGE: 50V
D601 D1501 = LED: LED GRN SGL 25MA SMT 0603; AGILE_PN: 370-76672; CAD_APPROVED: Yes; HEIGHT: 0.8 MM; MFG_NAME01: DIALIGHT; MFG_PN01: 598-8070-107F; ROHS: Yes; VOLTAGE: 2V
D1011 D1012 = DIODE: DIODE SCH 30V 200MA -- SOD323; AGILE_PN: 480-30039; CAD_APPROVED: Yes; HEIGHT: 1.15MM; MFG_NAME01: ON SEMICONDUCTOR; MFG_PN01: BAT54HT1G
D1502 = LED: LED OR SGL 20MA 0603; AGILE_PN: 370-76572; CAD_APPROVED: Yes; HEIGHT: 0.28MM; MFG_NAME01: KINGBRIGHT; MFG_PN01: APG1608SEKC/T; ROHS: Yes; Rated Voltage: 2V; Temp Range: -40°C to +85°C; Temp_Range: -40°C to +85°C; VOLTAGE: 2v
D1503 = ESD_DIODE_2LINE: DIODE BIDIR CAN BUS ESD PROTECTION 2.6A 24V AEC-Q101 SOT23; AGILE_PN: 480-80386; HEIGHT: 1.1MM; Package Size: TO-236-3, SC-59, SOT-23-3; Rated Voltage: 24V
J1501 = CONN_HDR_4X1: CON 1X4 SHRD TH 2MM SP 303H SN 126L; 3D_Mechanical_Footprint_File: http://www.hxdy.com/NewProductsLook.asp?id=18; AGILE_PN: 210-82576; CAD_APPROVED: Yes; HEIGHT: 7.7MM; MFG_NAME01: HONGXING ELECTRICAL; MFG_PN01: HX20020-4A; ROHS: Yes; Temp Range: -25 to +85°C
L1501 = DLW43: IND CHK 51uH@1MHZ 230mA -30%/+50% 1812; AGILE_PN: 180-78178; CAD_APPROVED: Yes; HEIGHT: 2.8MM; MFG_NAME01: MURATA; ROHS: Yes
R613 = RES: RES MF 1.0K 1/16W 1% 0402; AGILE_PN: 470-76037; CAD_APPROVED: Yes; FPLIST: RC0402_25,RC0402_HD,RC0402_X2,0402_CC; HEIGHT: 0.4MM; MFG_NAME01: VISHAY; MFG_PN01: CRCW04021K00FKEDC; ROHS: Yes; Tolerance: 1%; VOLTAGE: 1/16W
R1072 = RES: RES MF 1.0K 1/16W 5% 0402; AGILE_PN: 470-75555; CAD_APPROVED: Yes; FPLIST: RC0402_25,RC0402_HD,RC0402_X2,0402_CC; HEIGHT: 0.41mm; MFG_NAME01: VISHAY INTERTECHNOLOGY; MFG_PN01: CRCW04021K00JNED; RATING: 1/16W; ROHS: Yes; Tolerance: 5%
R1083 = RES: RES MF 330 OHM 1/16W 5% 0402; AGILE_PN: 470-75613; CAD_APPROVED: Yes; FPLIST: RC0402_25,RC0402_HD,0402_CC; HEIGHT: 0.41mm; MFG_NAME01: VISHAY INTERTECHNOLOGY; MFG_PN01: CRCW0402330RJNEA; ROHS: Yes; Tolerance: 5%
R1504 R1511 = RES: RES MF 62.0 OHM 1/8W 1% AEC-Q200 0603; AGILE_PN: 470-77889; CAD_APPROVED: Yes; FPLIST: RC0603_OV,RC0603,0603_CC; HEIGHT: 0.55MM; MFG_NAME01: KOA SPEER; MFG_PN01: RK73H1JTTD62R0F; ROHS: Yes; Temp Range: -55C to +155C; Tolerance: 1%
R1505 = RES: RES MF 2.2K 1/16W 5% 0402; AGILE_PN: 470-76602; CAD_APPROVED: Yes; FPLIST: RC0402_25,RC0402_HD,0402_CC; HEIGHT: 0.4 MM; MFG_NAME01: YAGEO AMERICA; MFG_PN01: RC0402JR-072K2L; RATING: 1/16W; ROHS: Yes; Tolerance: 5%
R1506 = RES: RES MF 1.0K 1/16W 5% 0402; AGILE_PN: 470-75555; CAD_APPROVED: Yes; FPLIST: RC0402_25,RC0402_HD,RC0402_X2,0402_CC,CAPC0402_L; HEIGHT: 0.41mm; MFG_NAME01: VISHAY INTERTECHNOLOGY; MFG_PN01: CRCW04021K00JNED; RATING: 1/16W; ROHS: Yes; Tolerance: 5%
R1507 R1510 = RES: RES MF ZERO OHM 1/16W 5% 0402; AGILE_PN: 470-75394; ASSY_OPT: DNP; CAD_APPROVED: Yes; FPLIST: RC0402_25,RC0402_HD,RC0402_X2,0402_CC; HEIGHT: 0.45 MM; MFG_NAME01: YAGEO AMERICA; MFG_PN01: RC0402JR-070RL; RATING: 1/16W; ROHS: Yes; Tolerance: 5%; VOLTAGE: 1/16W
R1508 R1509 = RES: RES MF ZERO OHM 1/16W 5% 0402; AGILE_PN: 470-75394; CAD_APPROVED: Yes; FPLIST: RC0402_25,RC0402_HD,RC0402_X2,0402_CC; HEIGHT: 0.45 MM; MFG_NAME01: YAGEO AMERICA; MFG_PN01: RC0402JR-070RL; RATING: 1/16W; ROHS: Yes; Tolerance: 5%; VOLTAGE: 1/16W
S1501 = SW-SPST_A: SW DIP 1 POS 0.025A@24VDC SMT; 3D_Mechanical_Footprint_File: ftp://fcl.am.freescale.net/ALLEGRO/step/sw_2p8x5p7_sm.step; AGILE_PN: 510-78408; CAD_APPROVED: Yes; HEIGHT: 2.5MM; MFG_NAME01: Nidec Copal Electronics Corporation; ROHS: Yes; Temp Range: -40C ~ 85C
TP1015-TP1021 = TESTLOOP: TEST POINT PAD 0.5MM DIA SMT, NO PART TO ORDER; AGILE_PN: 211-77484; ASSY_OPT: DNP; CAD_APPROVED: Yes; HEIGHT: 0.1MM; ROHS: Yes
U915 = P3T2108_6P: IC DIG TEMP SENSOR 12BIT I3C/I2C 12.5MHz/3.4MHz 1.4-3.6V WLCSP6; AGILE_PN: TMP-CIP-12138; HEIGHT: 0.485MM; MFG_NAME01: NXP SEMICONDUCTORS; MFG_PN01: P3T1085UKZ; PRE_APN: 312-83691; ROHS: Yes; Temp Range: -40°C to +125°C; VOLTAGE: 1.4-3.6V
U1004 = PCF2131_4: IC RTC CALENDAR W/XTAL TCXO 3.3V AEC-Q100 SO16; AGILE_PN: 312-82330; CAD_APPROVED: Yes; HEIGHT: 1.75MM; MFG_NAME01: NXP SEMICONDUCTORS; ROHS: Yes
U1501 = TJA1057GT3_8P: IC XCVR CAN 4.75-5.25V/2.95-5.25V AEC-Q100 SO8; 3D_Mechanical_Footprint_File: ftp://fcl.am.freescale.net/ALLEGRO/step/so8_1p27_4x5.step; AGILE_PN: 312-81479; CAD_APPROVED: Yes; HEIGHT: 1.75MM; MFG_NAME01: NXP SEMICONDUCTORS; ROHS: Yes; VOLTAGE: 4.75-5.25V/2.95-5.25V

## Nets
GND: BT1001.2(-) C201.2 C202.2 C203.2 C204.2 C205.2 C206.2 C207.2 C208.2 C209.2 C210.2 C211.2 C212.2 C213.2 C214.2 C215.2 C216.2 C217.2 C218.2 C219.2 C220.2 C221.2 C222.2 C701.1 C702.1 C703.2 C704.2 C705.2 C706.2 C707.2 C708.2 C709.1 C710.2 C711.2 C712.1 C713.1 C714.2 C715.2 C716.2 C717.2 C718.1 C719.2 C720.2 C721.1 C722.2 C723.2 C724.1 C725.2 C726.2 C727.2 C728.2 C729.2 C730.2 C731.2 C955.2 C956.2 C1021.2 C1022.2 C1023.2 C1024.2 C1501.2 C1502.2 C1503.2 C1504.1 C1505.2 C1506.2 C1507.2 C1508.2 C1509.2 D601.C(CATHODE) D1503.3(COM_CATHODE) J1501.4 R201.2 R204.2 R207.1 R208.1 R303.2 R718.2 R1078.1 R1079.1 TP615.1(TP) TP617.1(TP) U201.A3(VSS) U201.A10(VSS) U201.AB3(VSS) U201.AB5(VSS) U201.AB8(VSS) U201.AB10(VSS) U201.C1(VSS) U201.C5(VSS) U201.C8(VSS) U201.C12(VSS) U201.D2(VSS) U201.D4(VSS) U201.D9(VSS) U201.D11(VSS) U201.E1(VSS) U201.E5(VSS) U201.E8(VSS) U201.E12(VSS) U201.G1(VSS) U201.G3(VSS) U201.G5(VSS) U201.G8(VSS) U201.G10(VSS) U201.G12(VSS) U201.J1(VSS) U201.J3(VSS) U201.J10(VSS) U201.J12(VSS) U201.K2(VSS) U201.K4(VSS) U201.K9(VSS) U201.K11(VSS) U201.N2(VSS) U201.N4(VSS) U201.N9(VSS) U201.N11(VSS) U201.P1(VSS) U201.P3(VSS) U201.P10(VSS) U201.P12(VSS) U201.T1(VSS) U201.T3(VSS) U201.T5(VSS) U201.T8(VSS) U201.T10(VSS) U201.T12(VSS) U201.V1(VSS) U201.V5(VSS) U201.V8(VSS) U201.V12(VSS) U201.W2(VSS) U201.W4(VSS) U201.W9(VSS) U201.W11(VSS) U201.Y1(VSS) U201.Y5(VSS) U201.Y8(VSS) U201.Y12(VSS) U701.5(AGND) U701.43(BUCK_AGND) U701.57(EPAD) U915.A2(GND) U915.B1(A0) U1004.7(VSS) U1004.17(GND) U1501.2(GND) ; also on sheet 1 4 5 6 7 8 9 10 11 12 16 21 22 23
VBUS1_DET_3V3: R301.1 U101.B3(USB1_VBUS)
VDD_1V8: C201.1 C202.1 C203.1 C204.1 C205.1 C209.1 C719.1 C720.1 L705.2 R64.2 R65.2 TP707.1(TP) U201.F1(VDD1) U201.F12(VDD1) U201.G4(VDD1) U201.G9(VDD1) U201.T4(VDD1) U201.T9(VDD1) U201.U1(VDD1) U201.U12(VDD1) U701.14(BUCK5FB) ; also on sheet 5 6 7 8 9 12 16 21 22 23
VDD_3V3: C714.1 C715.1 C724.2 C955.1 C956.1 D1501.A(ANODE) D1502.A(ANODE) L704.2 R306.1 R307.1 R308.1 R309.1 R613.1 R705.1 R863.1 R1075.1 R1076.1 R1080.1 R1081.1 R1502.1 TP608.1(TP) TP706.1(TP) U701.21(BUCK4FB) U701.22(SWIN) U915.A1(VCC) ; also on sheet 5 6 7 8 9 10 11 12 16 21 22 23
VDD_5V: R1501.2 R1503.2 ; also on sheet 6 9 10 11 21
VDD_ANA_0V8: R871.2 TP712.1(TP) ; also on sheet 16
VDD_COIN_3V: BT1001.1(+) R1072.2 R1082.1
VDD_SOC_0V85: C707.1 C708.1 L702.2 R701.1 R709.1 R711.2 TP703.1(TP) ; also on sheet 16
VINT: C706.1 U701.4(VINT)
CAN1_RX: R1509.1 ; also on sheet 23
CAN1_TX: R1508.1 ; also on sheet 23
CAN_H: C1504.2 D1503.1(CATHODE1) J1501.2 L1501.2 R1504.2 R1507.2
CAN_L: C1509.1 D1503.2(CATHODE2) J1501.3 L1501.3 R1510.2 R1511.1
CAN_RX: R1505.2 R1509.2 U1501.4(RXD)
CAN_STBY: R1512.2 U1501.8(S) ; also on sheet 12
CAN_TX: R1506.2 R1508.2 U1501.1(TXD)
CAN_VDD_5V: C1501.1 C1502.1 R1501.1 U1501.3(VCC)
CAN_VIO_3V3: C1503.1 R1502.2 R1512.1 U1501.5(VIO)
CANH: L1501.1 R1507.1 U1501.7(CANH)
CANL: L1501.4 R1510.1 U1501.6(CANL)
DRAM_CA0_A: TP219.1(Pin1) U101.F1(DRAM_CA0_A) U201.H2(CA0_A)
DRAM_CA1_A: U101.E2(DRAM_CA1_A) U201.J2(CA1_A)
DRAM_CA2_A: U101.D2(DRAM_CA2_A) U201.H9(CA2_A)
DRAM_CA3_A: U101.C1(DRAM_CA3_A) U201.H10(CA3_A)
DRAM_CA4_A: U101.B2(DRAM_CA4_A) U201.H11(CA4_A)
DRAM_CA5_A: U101.A2(DRAM_CA5_A) U201.J11(CA5_A)
DRAM_CK_C_A: R205.2 U101.B1(DRAM_CK_C_A) U201.J9(CK_c_A)
DRAM_CK_T_A: R205.1 U101.C2(DRAM_CK_T_A) U201.J8(CK_t_A)
DRAM_CKE0_A: R207.2 U101.G1(DRAM_CKE0_A) U201.J4(CKE0_A)
DRAM_CKE1_A: R208.2 U101.F2(DRAM_CKE1_A) U201.J5(CKE1_A)
DRAM_DATA0_A: TP206.1(Pin1) U101.L2(DRAM_DQ00_A) U201.F4(DQ4_A)
DRAM_DATA1_A: TP207.1(Pin1) U101.L1(DRAM_DQ01_A) U201.E4(DQ5_A)
DRAM_DATA2_A: TP208.1(Pin1) U101.K2(DRAM_DQ02_A) U201.C4(DQ6_A)
DRAM_DATA3_A: TP209.1(Pin1) U101.K1(DRAM_DQ03_A) U201.B4(DQ7_A)
DRAM_DATA4_A: TP202.1(Pin1) U101.J1(DRAM_DQ04_A) U201.B2(DQ0_A)
DRAM_DATA5_A: TP203.1(Pin1) U101.H2(DRAM_DQ05_A) U201.C2(DQ1_A)
DRAM_DATA6_A: TP204.1(Pin1) U101.H1(DRAM_DQ06_A) U201.E2(DQ2_A)
DRAM_DATA7_A: TP205.1(Pin1) U101.G2(DRAM_DQ07_A) U201.F2(DQ3_A)
DRAM_DATA8_A: TP212.1(Pin1) U101.T2(DRAM_DQ08_A) U201.E11(DQ10_A)
DRAM_DATA9_A: TP213.1(Pin1) U101.U2(DRAM_DQ09_A) U201.F11(DQ11_A)
DRAM_DATA10_A: TP211.1(Pin1) U101.T1(DRAM_DQ10_A) U201.C11(DQ9_A)
DRAM_DATA11_A: TP210.1(Pin1) U101.R2(DRAM_DQ11_A) U201.B11(DQ8_A)
DRAM_DATA12_A: TP216.1(Pin1) U101.N1(DRAM_DQ12_A) U201.C9(DQ14_A)
DRAM_DATA13_A: TP217.1(Pin1) U101.N2(DRAM_DQ13_A) U201.B9(DQ15_A)
DRAM_DATA14_A: TP215.1(Pin1) U101.M2(DRAM_DQ14_A) U201.E9(DQ13_A)
DRAM_DATA15_A: TP214.1(Pin1) U101.M1(DRAM_DQ15_A) U201.F9(DQ12_A)
DRAM_DMI0_A: TP201.1(Pin1) U101.J2(DRAM_DMI0_A) U201.C3(DMI0_A)
DRAM_DMI1_A: U101.R1(DRAM_DMI1_A) U201.C10(DMI1_A)
DRAM_nCS0_A: TP218.1(Pin1) U101.D1(DRAM_CS0_A) U201.H4(CS0_A)
DRAM_nCS1_A: U101.E1(DRAM_CS1_A) U201.H3(CS1_A)
DRAM_nRESET: R102.1 R201.1 U101.F4(DRAM_RESET_N) U201.T11(RESET_N)
DRAM_SDQS0_C_A: U101.K4(DRAM_DQS0_C_A) U201.E3(DQS0_c_A)
DRAM_SDQS0_T_A: U101.M4(DRAM_DQS0_T_A) U201.D3(DQS0_t_A)
DRAM_SDQS1_C_A: U101.P2(DRAM_DQS1_C_A) U201.E10(DQS1_c_A)
DRAM_SDQS1_T_A: U101.P1(DRAM_DQS1_T_A) U201.D10(DQS1_t_A)
DRAM_ZN: R204.1 U101.H4(DRAM_ZQ)
DRAM_ZQ0: R209.2 U201.A5(ZQ0)
ENET1_MDC: U101.T8(ENET1_MDC) ; also on sheet 8
ENET1_MDIO: U101.U7(ENET1_MDIO) ; also on sheet 8
ENET1_RD0: U101.U5(ENET1_RD0) ; also on sheet 8
ENET1_RD1: U101.T6(ENET1_RD1) ; also on sheet 8
ENET1_RD2: U101.U6(ENET1_RD2) ; also on sheet 8
ENET1_RD3: U101.T7(ENET1_RD3) ; also on sheet 8
ENET1_RX_CTL: U101.T5(ENET1_RX_CTL) ; also on sheet 8
ENET1_RXC: U101.U4(ENET1_RXC) ; also on sheet 8
ENET1_TD0: TP221.1(Pin1) U101.U9(ENET1_TD0) ; also on sheet 8
ENET1_TD1: U101.R9(ENET1_TD1) ; also on sheet 8
ENET1_TD2: U101.U10(ENET1_TD2) ; also on sheet 8
ENET1_TD3: U101.T10(ENET1_TD3) ; also on sheet 8
ENET1_TX_CTL: U101.T9(ENET1_TX_CTL) ; also on sheet 8
ENET1_TXC: TP220.1(Pin1) U101.U8(ENET1_TXC) ; also on sheet 8
GPIO_IO00: U101.B16(GPIO_IO00) ; also on sheet 21
GPIO_IO01: U101.B17(GPIO_IO01) ; also on sheet 21
GPIO_IO02: U101.C16(GPIO_IO02) ; also on sheet 21
GPIO_IO03: U101.C17(GPIO_IO03) ; also on sheet 21
GPIO_IO04: U101.D16(GPIO_IO04) ; also on sheet 21
GPIO_IO05: U101.D17(GPIO_IO05) ; also on sheet 21
GPIO_IO06: U101.E16(GPIO_IO06) ; also on sheet 21
GPIO_IO07: U101.E17(GPIO_IO07) ; also on sheet 21
GPIO_IO08: U101.K14(GPIO_IO08) ; also on sheet 12
GPIO_IO09: U101.F16(GPIO_IO09) ; also on sheet 12
GPIO_IO10: U101.F17(GPIO_IO10) ; also on sheet 12
GPIO_IO11: U101.G16(GPIO_IO11) ; also on sheet 12
GPIO_IO12: U101.F14(GPIO_IO12) ; also on sheet 12
GPIO_IO13: U101.G17(GPIO_IO13) ; also on sheet 21
GPIO_IO14: U101.H16(GPIO_IO14) ; also on sheet 21
GPIO_IO15: U101.H17(GPIO_IO15) ; also on sheet 21
GPIO_IO16: U101.J16(GPIO_IO16) ; also on sheet 12
GPIO_IO17: U101.K15(GPIO_IO17) ; also on sheet 12
GPIO_IO18: U101.M14(GPIO_IO18) ; also on sheet 12
GPIO_IO19: U101.J17(GPIO_IO19) ; also on sheet 12
GPIO_IO20: U101.K16(GPIO_IO20) ; also on sheet 12
GPIO_IO21: U101.K17(GPIO_IO21) ; also on sheet 12
I2C1_SCL: R163.2 R307.2 R717.1 U101.A12(I2C1_SCL) ; also on sheet 6 7 10 12 21
I2C1_SCLL: R65.1 R713.2 ; also on sheet 7
I2C1_SDA: R164.2 R306.2 R719.1 U101.B12(I2C1_SDA) ; also on sheet 6 7 10 12 21
I2C1_SDAL: R64.1 R712.2 ; also on sheet 7
I2C2_SCL: R309.2 R714.1 U101.A11(I2C2_SCL) ; also on sheet 12
I2C2_SDA: R308.2 R715.1 U101.B11(I2C2_SDA) ; also on sheet 12
I3C1_SCL: R163.1 R861.1 ; also on sheet 21
I3C1_SDA: R164.1 R862.1 ; also on sheet 21
LPD4/x_VDD2_1V1: C206.1 C207.1 C208.1 C210.1 C211.1 C212.1 C213.1 C214.1 C722.1 C723.1 L706.2 R210.1 R702.1 TP708.1(TP) U201.A4(VDD2) U201.A9(VDD2) U201.AB4(VDD2) U201.AB9(VDD2) U201.F5(VDD2) U201.F8(VDD2) U201.H1(VDD2) U201.H5(VDD2) U201.H8(VDD2) U201.H12(VDD2) U201.K1(VDD2) U201.K3(VDD2) U201.K10(VDD2) U201.K12(VDD2) U201.N1(VDD2) U201.N3(VDD2) U201.N10(VDD2) U201.N12(VDD2) U201.R1(VDD2) U201.R5(VDD2) U201.R8(VDD2) U201.R12(VDD2) U201.U5(VDD2) U201.U8(VDD2) U701.52(BUCK6FB) ; also on sheet 16
LPD4/x_VDDQ_0V6: C215.1 C216.1 C217.1 C218.1 C219.1 C220.1 C221.1 C222.1 R209.1 R211.2 R702.2 R704.2 TP702.1(TP) U201.AA3(VDDQ) U201.AA5(VDDQ) U201.AA8(VDDQ) U201.AA10(VDDQ) U201.B3(VDDQ) U201.B5(VDDQ) U201.B8(VDDQ) U201.B10(VDDQ) U201.D1(VDDQ) U201.D5(VDDQ) U201.D8(VDDQ) U201.D12(VDDQ) U201.F3(VDDQ) U201.F10(VDDQ) U201.U3(VDDQ) U201.U10(VDDQ) U201.W1(VDDQ) U201.W5(VDDQ) U201.W8(VDDQ) U201.W12(VDDQ) ; also on sheet 16
LPD4x_VDDQ_0V6: C703.1 C705.1 L701.2 R704.1 U701.44(R_SNSP2)
NVCC_BBSM_1V8: C727.1 R703.1 TP709.1(TP) U701.3(LDO1) ; also on sheet 1 16 21
NVCC_SD2: C731.1 R310.1 R311.1 R312.1 TP713.1(TP) U701.55(LDO5) ; also on sheet 16 22
ODT_CA_A: R210.2 U201.G2(ODT_CA_A)
PDM_CLK: U101.A16(PDM_CLK) ; also on sheet 23
PDM_DATA0: U101.A10(PDM_BIT_STREAM0) ; also on sheet 23
PDM_DATA1: U101.B10(PDM_BIT_STREAM1) ; also on sheet 23
PMIC_32K_OUT: U701.7(CLK_32K_OUT) ; also on sheet 1 7
PMIC_nINT: U701.13(IRQ_B) ; also on sheet 12
PMIC_ON_REQ: R707.1 ; also on sheet 1 5 11
PMIC_STBY_REQ: R708.1 ; also on sheet 1 5
POR_B: U701.9(POR_B) ; also on sheet 1 5 12
RTC_CLKO: TP1021.1(Pin1) U1004.6(CLKOUT) ; also on sheet 7
RTC_nINTA: R1075.2 R1084.1 TP1019.1(Pin1) U1004.13(~{INTA}) ; also on sheet 12
SAI1_RXD0: U101.B14(SAI1_RXD0) ; also on sheet 7
SAI1_TXC: U101.B15(SAI1_TXC) ; also on sheet 7
SAI1_TXD0: U101.A15(SAI1_TXD0) ; also on sheet 7 23
SAI1_TXFS: U101.A14(SAI1_TXFS) ; also on sheet 7 23
SD1_CLK: U101.U11(SD1_CLK) ; also on sheet 22
SD1_CMD: U101.T11(SD1_CMD) ; also on sheet 22
SD1_DATA0: U101.T13(SD1_DATA0) ; also on sheet 22
SD1_DATA1: U101.T14(SD1_DATA1) ; also on sheet 22
SD1_DATA2: U101.T15(SD1_DATA2) ; also on sheet 22
SD1_DATA3: U101.U13(SD1_DATA3) ; also on sheet 22
SD1_DATA4: U101.T12(SD1_DATA4) ; also on sheet 22
SD1_DATA5: U101.U14(SD1_DATA5) ; also on sheet 22
SD1_DATA6: U101.U15(SD1_DATA6) ; also on sheet 22
SD1_DATA7: U101.U16(SD1_DATA7) ; also on sheet 22
SD1_STROBE: U101.U12(SD1_STROBE) ; also on sheet 22
SD2_CLK: U101.M16(SD2_CLK) ; also on sheet 22
SD2_CMD: R311.2 U101.M17(SD2_CMD) ; also on sheet 22
SD2_DATA0: R310.2 U101.N17(SD2_DATA0) ; also on sheet 22
SD2_DATA1: U101.N16(SD2_DATA1) ; also on sheet 22
SD2_DATA2: U101.L17(SD2_DATA2) ; also on sheet 22
SD2_DATA3: U101.L16(SD2_DATA3) ; also on sheet 22
SD2_nCD: U101.P12(SD2_CD_B) ; also on sheet 22
SD2_nRST: R312.2 R723.2 U101.P10(SD2_RESET_B)
SD2_VSEL: U101.P14(SD2_VSELECT) U701.29(SD_VSEL)
SD3_CLK: U101.T16(SD3_CLK) ; also on sheet 7
SD3_CMD: U101.T17(SD3_CMD) ; also on sheet 7
SD3_DATA0: U101.R16(SD3_DATA0) ; also on sheet 7
SD3_DATA1: U101.R17(SD3_DATA1) ; also on sheet 7
SD3_DATA2: U101.P16(SD3_DATA2) ; also on sheet 7
SD3_DATA3: U101.P17(SD3_DATA3) ; also on sheet 7
SYS_nRST: R706.1 R1085.2 TP915.1(TP) ; also on sheet 5 21
TEMP_SCL: R861.2 U915.B2(SCL)
TEMP_SDA: R862.2 U915.C2(SDA)
UART1_RXD: TP612.1(TP) U101.B13(UART1_RXD) ; also on sheet 5
UART1_TXD: TP610.1(TP) U101.A13(UART1_TXD) ; also on sheet 5 23
UART2_RXD: TP616.1(TP) U101.D14(UART2_RXD) ; also on sheet 5
UART2_TXD: TP614.1(TP) U101.D12(UART2_TXD) ; also on sheet 5 23
USB1_DN: TP611.1(TP) U101.A4(USB1_D_N) ; also on sheet 9
USB1_DP: TP613.1(TP) U101.B4(USB1_D_P) ; also on sheet 9
USB1_ID: U101.D4(USB1_ID) ; also on sheet 9
USB1_VBUS_3V3: R301.2 ; also on sheet 9
USB_I2C_SCL: R1073.1 ; also on sheet 9 10
USB_I2C_SDA: R1074.1 ; also on sheet 9 10
USBC_VBUS: TP609.1(TP) ; also on sheet 9
VBBS: C1021.1 U1004.14(BBS)
VCAN_5V: C1505.1 C1506.1 J1501.1 R1503.1
VLDO3_1V8: C729.1 TP711.1(TP) U701.54(NC_2) ; also on sheet 16
VLDO_3V3: D1011.A(ANODE) D1012.A(ANODE) R1077.1 ; also on sheet 9 10
VSD_3V3: C725.1 U701.23(SWOUT) ; also on sheet 22
VSYS_5V: C701.2 C702.2 C704.1 C709.2 C712.2 C713.2 C718.2 C721.2 C726.1 TP607.1(TP) U701.16(INB45_1) U701.17(INB45_2) U701.18(INB45_3) U701.33(INB13_1) U701.34(INB13_2) U701.35(INB13_3) U701.47(INB26_1) U701.48(INB26_2) U701.49(INB26_3) U701.53(VSYS) U701.56(INL1) ; also on sheet 7 9 11
WDOG_B: R710.1 TP916.1(TP) U101.H14(WDOG_ANY) ; also on sheet 5
XIN_32K: C716.1 QZ701.2 R720.1 U701.10(XTAL_IN)
XOUT_32K: C717.1 QZ701.1 R720.2 U701.11(XTAL_OUT)
N111682856: C1507.1 R1504.1 S1501.2(COMMON)
N111682880: D1501.C(CATHODE) R1505.1
N111682886: D1502.C(CATHODE) R1506.1
N111683153: C1508.1 R1511.2 S1501.1(NC)
N113526638: L701.1 U701.45(LX2_1) U701.46(LX2_2)
N113526990: L702.1 U701.36(LX1_1) U701.37(LX1_2)
N113527145: R701.2 R711.1 U701.38(R_SNSP1)
N113527183: C710.1 C711.1 L703.2 R709.2 R716.1
N113527270: L703.1 U701.31(LX3_1) U701.32(LX3_2)
N113527381: R716.2 R718.1 U701.30(R_SNSP3_CFG)
N113527504: L704.1 U701.19(LX4_1) U701.20(LX4_2)
N113527663: L705.1 U701.15(LX5)
N113527832: L706.1 U701.50(LX6_1) U701.51(LX6_2)
N113528020: R723.1 U701.12(SW_EN)
N113528254: C728.1 TP710.1(TP) U701.2(NC_1)
N113528336: C730.1 R871.1 U701.1(LDO4)
N114629076: R703.2 R706.2 U701.8(PMIC_RST_B)
N114629170: R705.2 R710.2 U701.28(WDOG_B)
N114629754: R707.2 U701.39(PMIC_ON_REQ)
N114629773: R708.2 U701.40(PMIC_STBY_REQ)
N114629886: R715.2 U701.42(SDA)
N114629887: R714.2 U701.41(SCL)
N114636326: TP714.1(TP) U701.6(RTC_RESET_B)
N115575393: R303.1 U101.A3(USB1_TXRTUNE)
N115788648: D601.A(ANODE) R613.2
N116167004: C1023.1 C1024.1 R1083.2 U1004.15(VDD)
N116167167: D1012.C(CATHODE) R1072.1
N116167227: C1022.1 R1082.2 U1004.16(VBAT)
N116167406: R1077.2 U1004.1(IFS)
N116167434: R1073.2 R1080.2 U1004.2(SCL)
N116167436: R1074.2 R1081.2 U1004.5(SDA/~{CE})
N116167463: R1076.2 R1084.2 R1085.1 TP1020.1(Pin1) U1004.12(~{INTB})
N116167513: R1078.2 U1004.3(SDI)
N116167550: R1079.2 U1004.4(SDO)
N116167586: TP1015.1(Pin1) U1004.8(~{TS1})
N116167598: TP1016.1(Pin1) U1004.9(~{TS2})
N116167606: TP1017.1(Pin1) U1004.10(~{TS3})
N116167616: TP1018.1(Pin1) U1004.11(~{TS4})
N116260997: R863.2 TP1954.1(TP) U915.C1(~{ALERT})
N116323997: D1011.C(CATHODE) R1083.1
N116421020: R211.1 U201.A8(ZQ1)
N116438273: R719.2 U701.24(SDAH)
N116438275: R717.2 U701.25(SCLH)
N116438398: R713.1 U701.27(SCLL)
N116438407: R712.1 U701.26(SDAL)
N116479778: R102.2 U201.G11(NC)

Not connected (* = marked no-connect by the designer): U201 A1(DNU)* A2(DNU)* A11(DNU)* A12(DNU)* AA1(DNU)* AA2(DQ0_B)* AA4(DQ7_B)* AA9(DQ15_B)* AA11(DQ8_B)* AA12(DNU)* AB1(DNU)* AB2(DNU)* AB11(DNU)* AB12(DNU)* B1(DNU)* B12(DNU)* K5(NC)* K8(NC)* N5(NC)* N8(NC)* P2(CA1_B)* P4(CKE0_B)* P5(CKE1_B)* P8(CK_t_B)* P9(CK_c_B)* P11(CA5_B)* R2(CA0_B)* R3(CS1_B)* R4(CS0_B)* R9(CA2_B)* R10(CA3_B)* R11(CA4_B)* T2(ODT_CA_B)* U2(DQ3_B)* U4(DQ4_B)* U9(DQ12_B)* U11(DQ11_B)* V2(DQ2_B)* V3(DQS0_c_B)* V4(DQ5_B)* V9(DQ13_B)* V10(DQS1_c_B)* V11(DQ10_B)* W3(DQS0_t_B)* W10(DQS1_t_B)* Y2(DQ1_B)* Y3(DMI0_B)* Y4(DQ6_B)* Y9(DQ14_B)* Y10(DMI1_B)* Y11(DQ9_B)*

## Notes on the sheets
sheet 17
- SYS PMIC
- 0.6V-2.1875V / 12.5mV
- 3A / 0.8V  DVS
- Sense from Processor power pin
- # System Reset Button
- 3A / 0.8V  DVS
- OD+PU<LDO1>
- 0.6V-2.1875V / 12.5mV
- OD
- OD
- Sense from Processor power pin
- # BUCK1&3 Dual Phase Mode
- 3A / 0.8V  DVS
- 0.6V-2.1875V / 12.5mV
- Sense connect to GND for dual phase mode
- <LDO1>
- 3A / 3.3V
- 0.6V-3.4V / 25mV
- I2C ADDR: 0x25 (010 0101x)
- Add PU if using level translator (per DS). Float if unused.
- Note:
- 2A / 1.8V
- 1. PMIC_RST_B is used as Cold Reset as default.
- 0.6V-3.4V / 25mV
- 2. WDOG_B is used as Cold Reset, external pull up is needed for BSDL mode.
- PMIC: PCA9451AHN  CFG
- 2A / 1.1V
- SEQ
- REGULATOR
- VOL (V)
- MAX I (mA)
- PWR RAIL
- TYP VOL(V)
- REQ I (mA)
- 0.6V-3.4V / 25mV
- tstep=2ms
- 1
- LDO1
- 1.8
- 10
- NVCC_BBSM_1V8
- 1.8
- 2
- -
- -
- PMIC_ON_REQ
- 400mA / 3.3V
- 2
- T1
- BUCK1/3 DP
- 0.85
- 4000
- VDD_SOC
- DVS
- Ref to DS
- 3
- T2
- LDO4
- 0.8
- 200
- VDD_ANA_0P8
  VDD_MIPI_0P8
  VDD_USB_0P8
- 0.8
- 186
- 4
- 5
- T4
- BUCK5
- 1.8
- 2000
- VDD_ANAx_1P8
  VDD_LVDS_1P8
  VDD_MIPI_1P8
  VDD_USB_1P8
  NVCC_GPIO
- 1.8
- 1040
- 10mA / 1.8V
- PERI INCLUDE
- 1.6V-1.9V
  3.0V-3.3V / 100mV
- Note:
- 6
- T5
- BUCK6
- 1.1
- 1500
- VDD2_DDR
  VDDQ_DDR (1.1V for LPD4)
- 1.1
- 676
- PIN2/54 is NC, C728/C729 just keep the compatible with previous design.
- 7
- T6
- BUCK2
- 0.6
- 2000
- VDDQ_DDR (0.6V for LPD4x)
- 0.6
- 360
- 8
- T7
- BUCK4
- 3.3
- 3000
- NVCC_GPIO
  VDD_USB_3P3
- 3.3
- 2870
- PERI INCLUDE
- 200mA / 3.3V
- 8
- T7
- Load Switch
- -
- 400
- SD_CARD (from BUCK4 )
- 3.3
- 0.8V-3.3V / 100mV
- 9
- T8
- LDO5
- 1.8/3.3
- 150
- NVCC_SD2
- 1.8/3.3
- -
- -
- 150mA / (3.3V/1.8V)
- 1.8V-3.3V / 100mV
- 12
- POR_B
- --
- --
- POR_B
sheet 18
- LPDDR4/X
- # VDD1: 1.8V /400mA
- # VDD2 : 1.1V / 600mA
- # VDDQ: (0.6V/1.1V) / 360mA
- #0.6V for LPDDR4X
- #1.1V for LPDDR4
- LPDDR4X: 2GB (x16)
- Z:85 OHM
- Z:85 OHM
- # Power Supply Voltage Sequence:
- RESET_n is held LOW.
  VDD1 >= VDD2
  VDD2 >= VDDQ-200mV
- Z:85 OHM
- Power ramp duration tINIT0 (Tb¨CTa) must not exceed 20ms.
- # ZQ1 is reserved for 2CS LPDDR4/x
- For 100-ball LPDDR4/X
sheet 19
- CAN BUS
- Standby: 5 uA
- Split termination for RC tee filter
- fc=1/[2*pie*(Rt/2)*Csplit]
- TDK:B82793S0513N201
  ACT45B-510-2P-TL003
- Z:120 OHM
- # Compatible : TJA1051T/3
- RSUP and CSUP: An appropriate RC filter needs to be
  added to guarantee the chip will only see <0.35 V/ms ramp
  down rate on supply, even if Vdd_in ramp rate is very high.
- RSUP
- CSUP
- #Coin Cell charge circuits, ONLY
  DESIGNED FOR RECHARGEABLE
  COINE CELL BATTERY!!!.
- I3C TEMP SENSOR
- 1.0mAh (3.1V ～2.0V)
  DSC 0.005mA
- Ext. RTC
- # If RTC kept during system OFF,
  Coin Cell BT1001 and R1082 need to be installed
- OD
- #I2C ADDR: 0b'1001000x
- #I2C ADDR: 0b'1010011x
- #A55 DBG
- #M33 DBG
- # USB Serial Download
sheet 20
- i.MX93 IO/PHY
- #eMMC
- #ENET1
- #M.2
- USB Z:90 OHM
- #USB1 C DRP
- #MicroSD
- PHY
- Note:
- If USB connector is MicroAB or MicroB, USBx_VBUS MUST not connect directly to the 5V VBUS voltage
  of connector. Instead, this pin must be isloated with an external 30K 1% resistor.
- I3C
- External PU is necessary for SD2_RESET_B to enable SD card power as default!
